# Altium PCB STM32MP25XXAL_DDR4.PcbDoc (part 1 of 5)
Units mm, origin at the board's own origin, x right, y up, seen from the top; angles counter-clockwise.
Board outline 125 x 95 mm, 6 copper layers (Top Layer, Signal Layer 1, Signal Layer 2, Signal Layer 3, Signal Layer 4, Bottom Layer), stack 1.403 mm thick; 220 components, 316 nets, 1103 pads, 939 vias.
Unrouted connection lines stored in the file: 5.
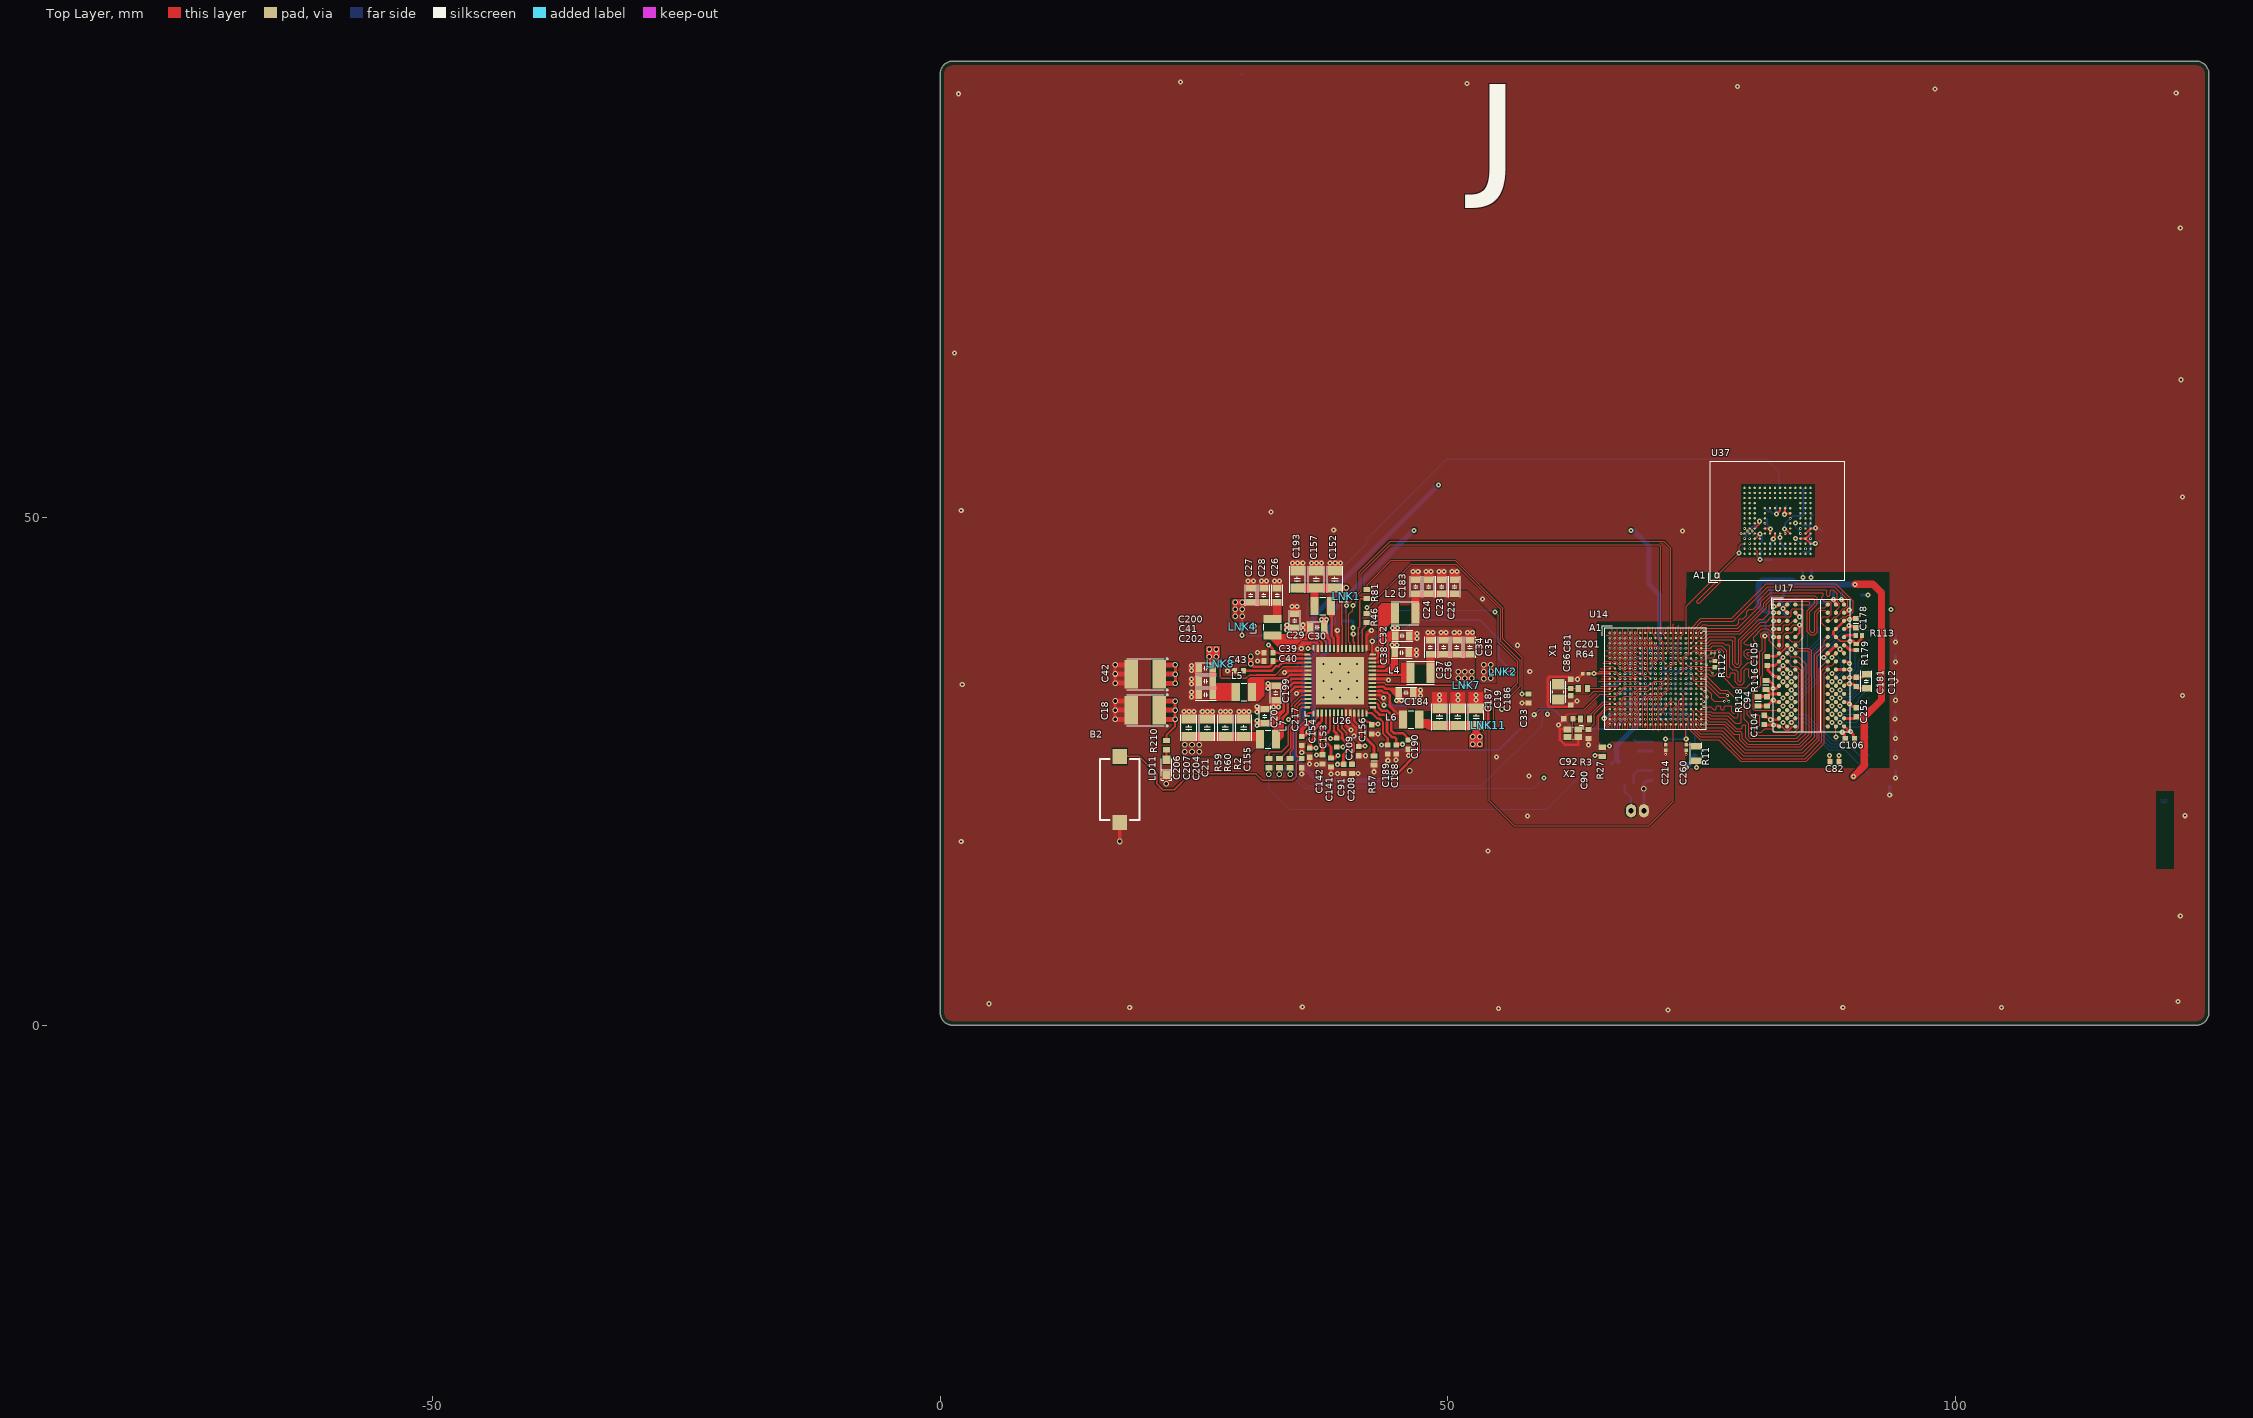
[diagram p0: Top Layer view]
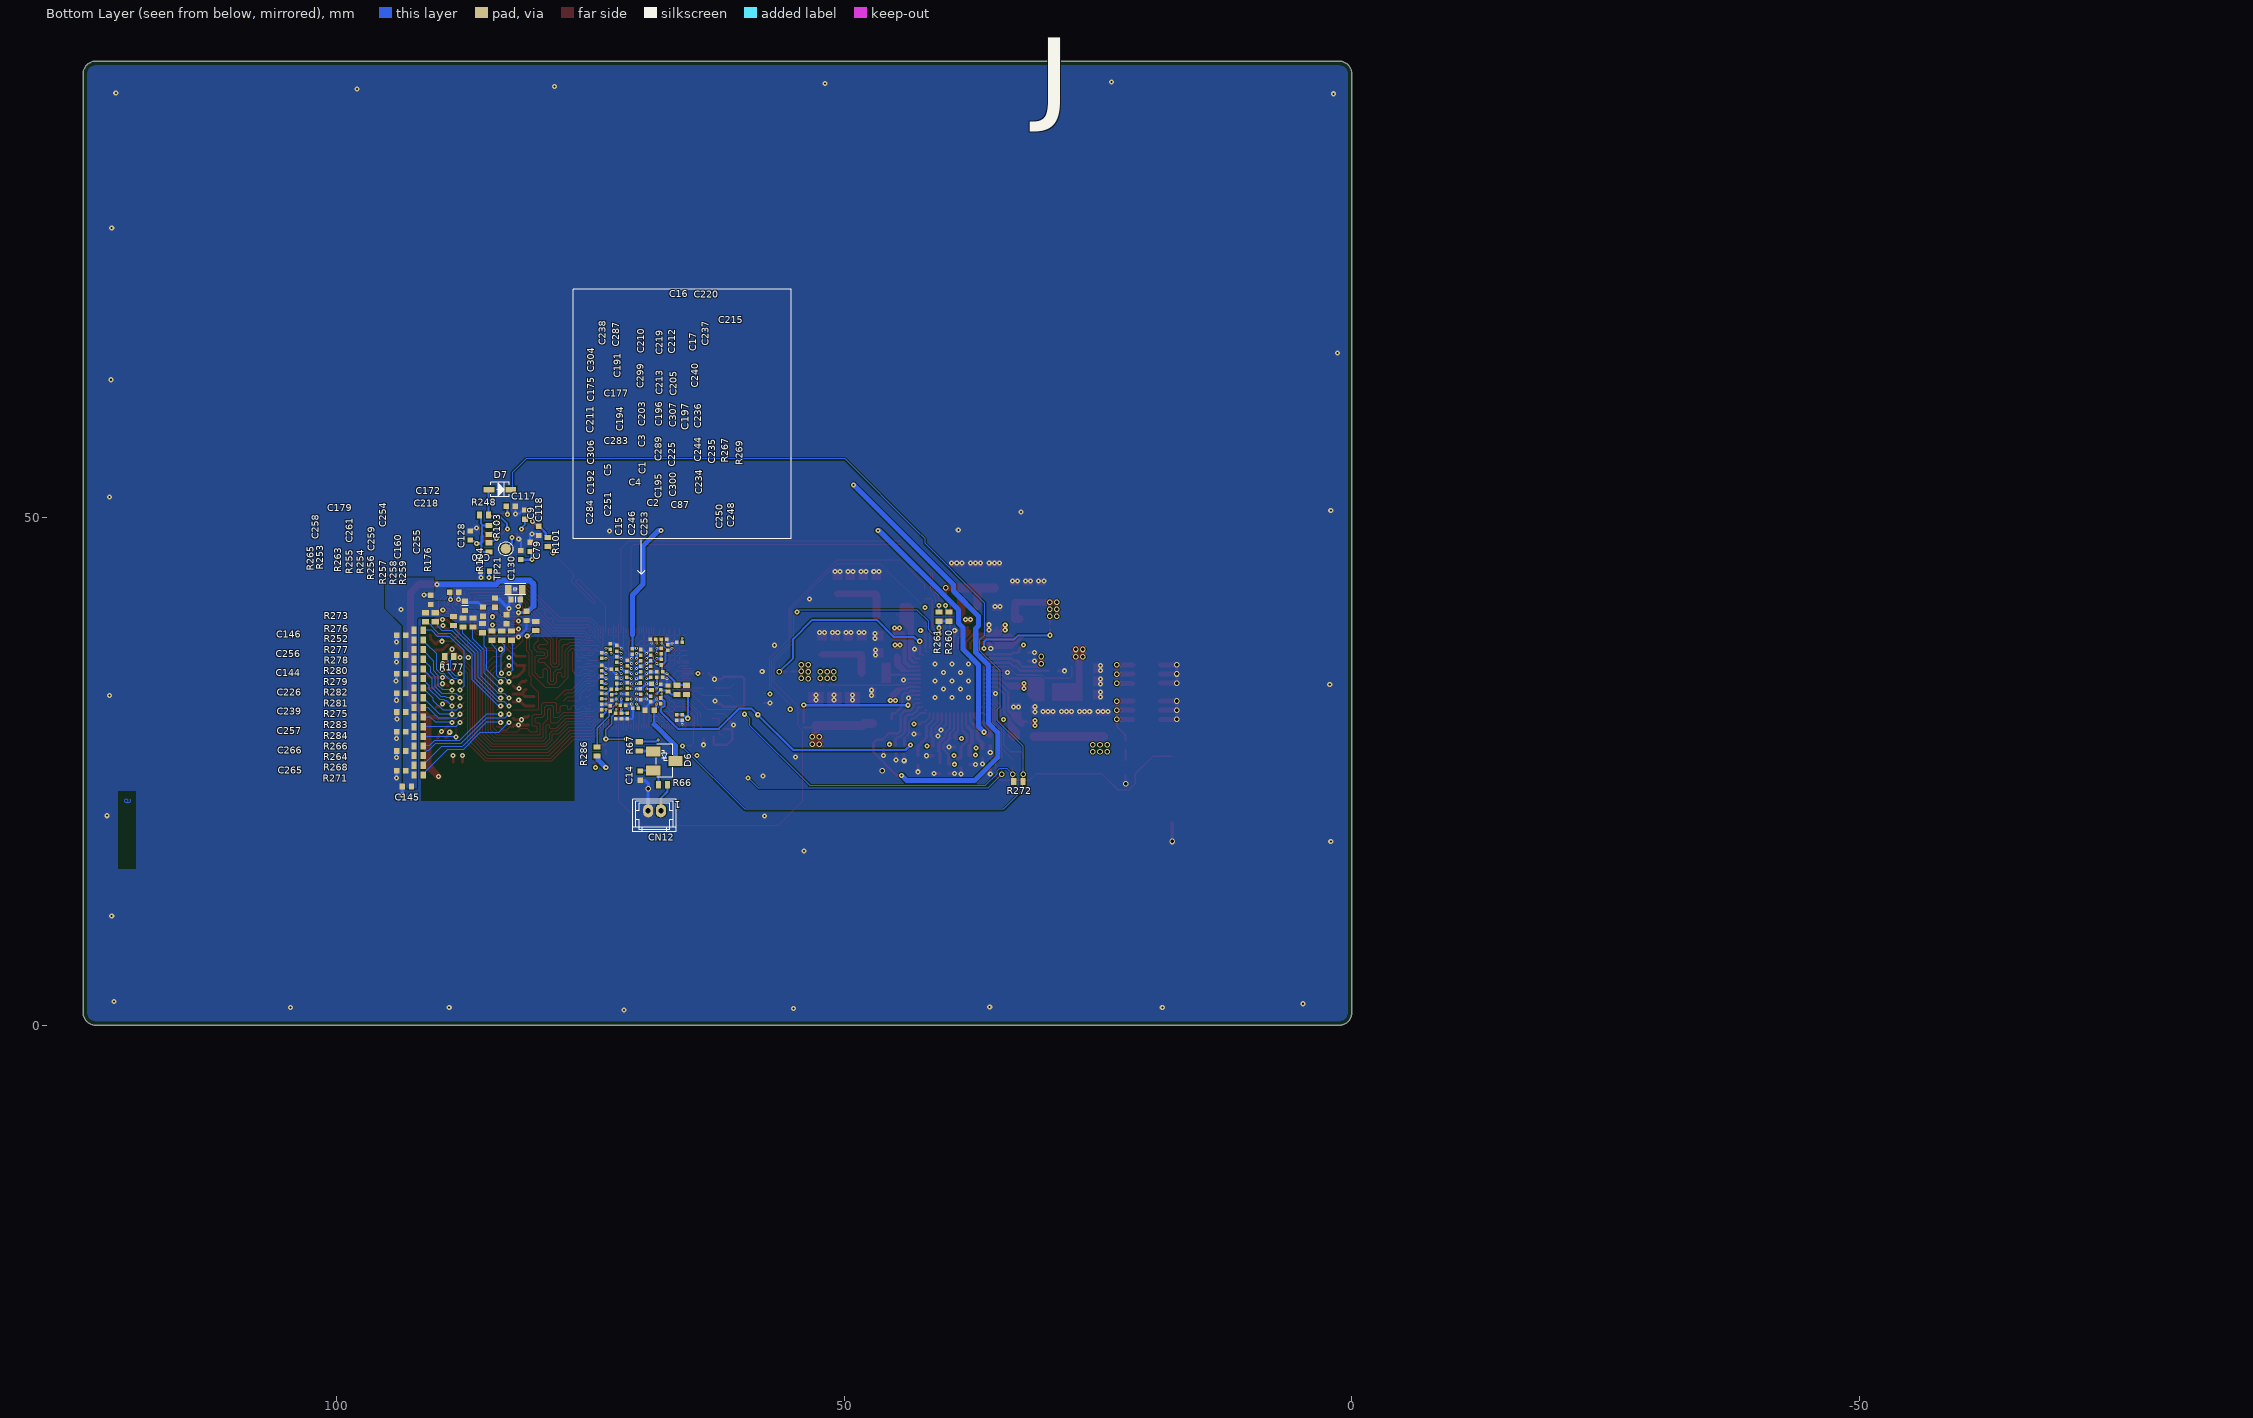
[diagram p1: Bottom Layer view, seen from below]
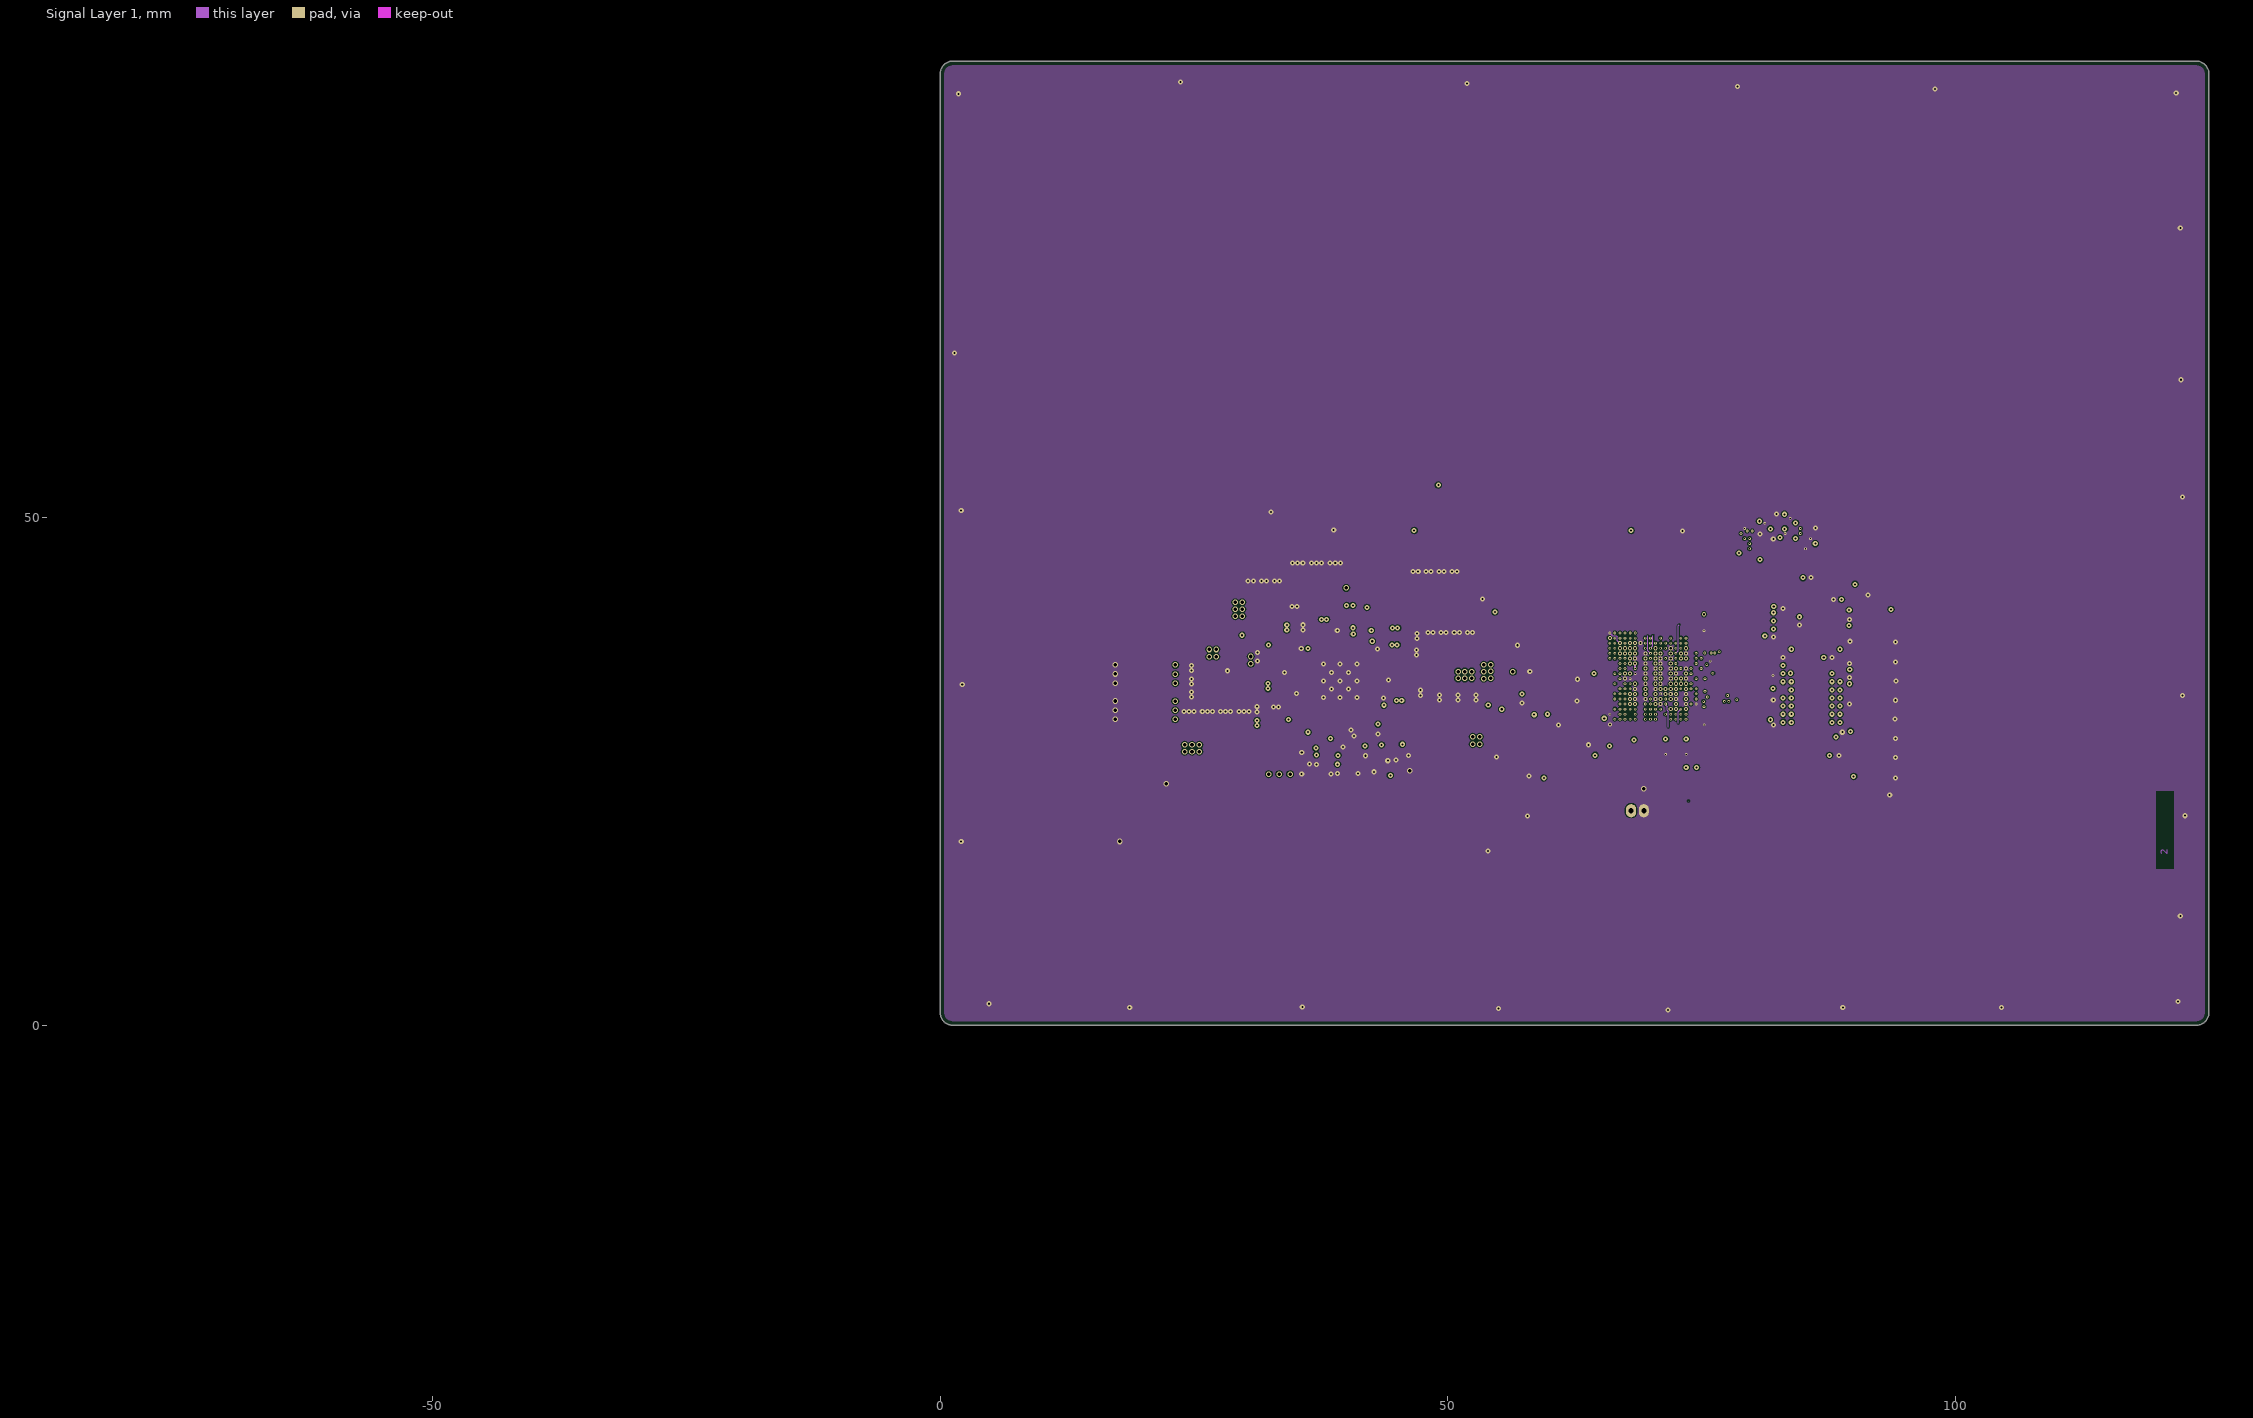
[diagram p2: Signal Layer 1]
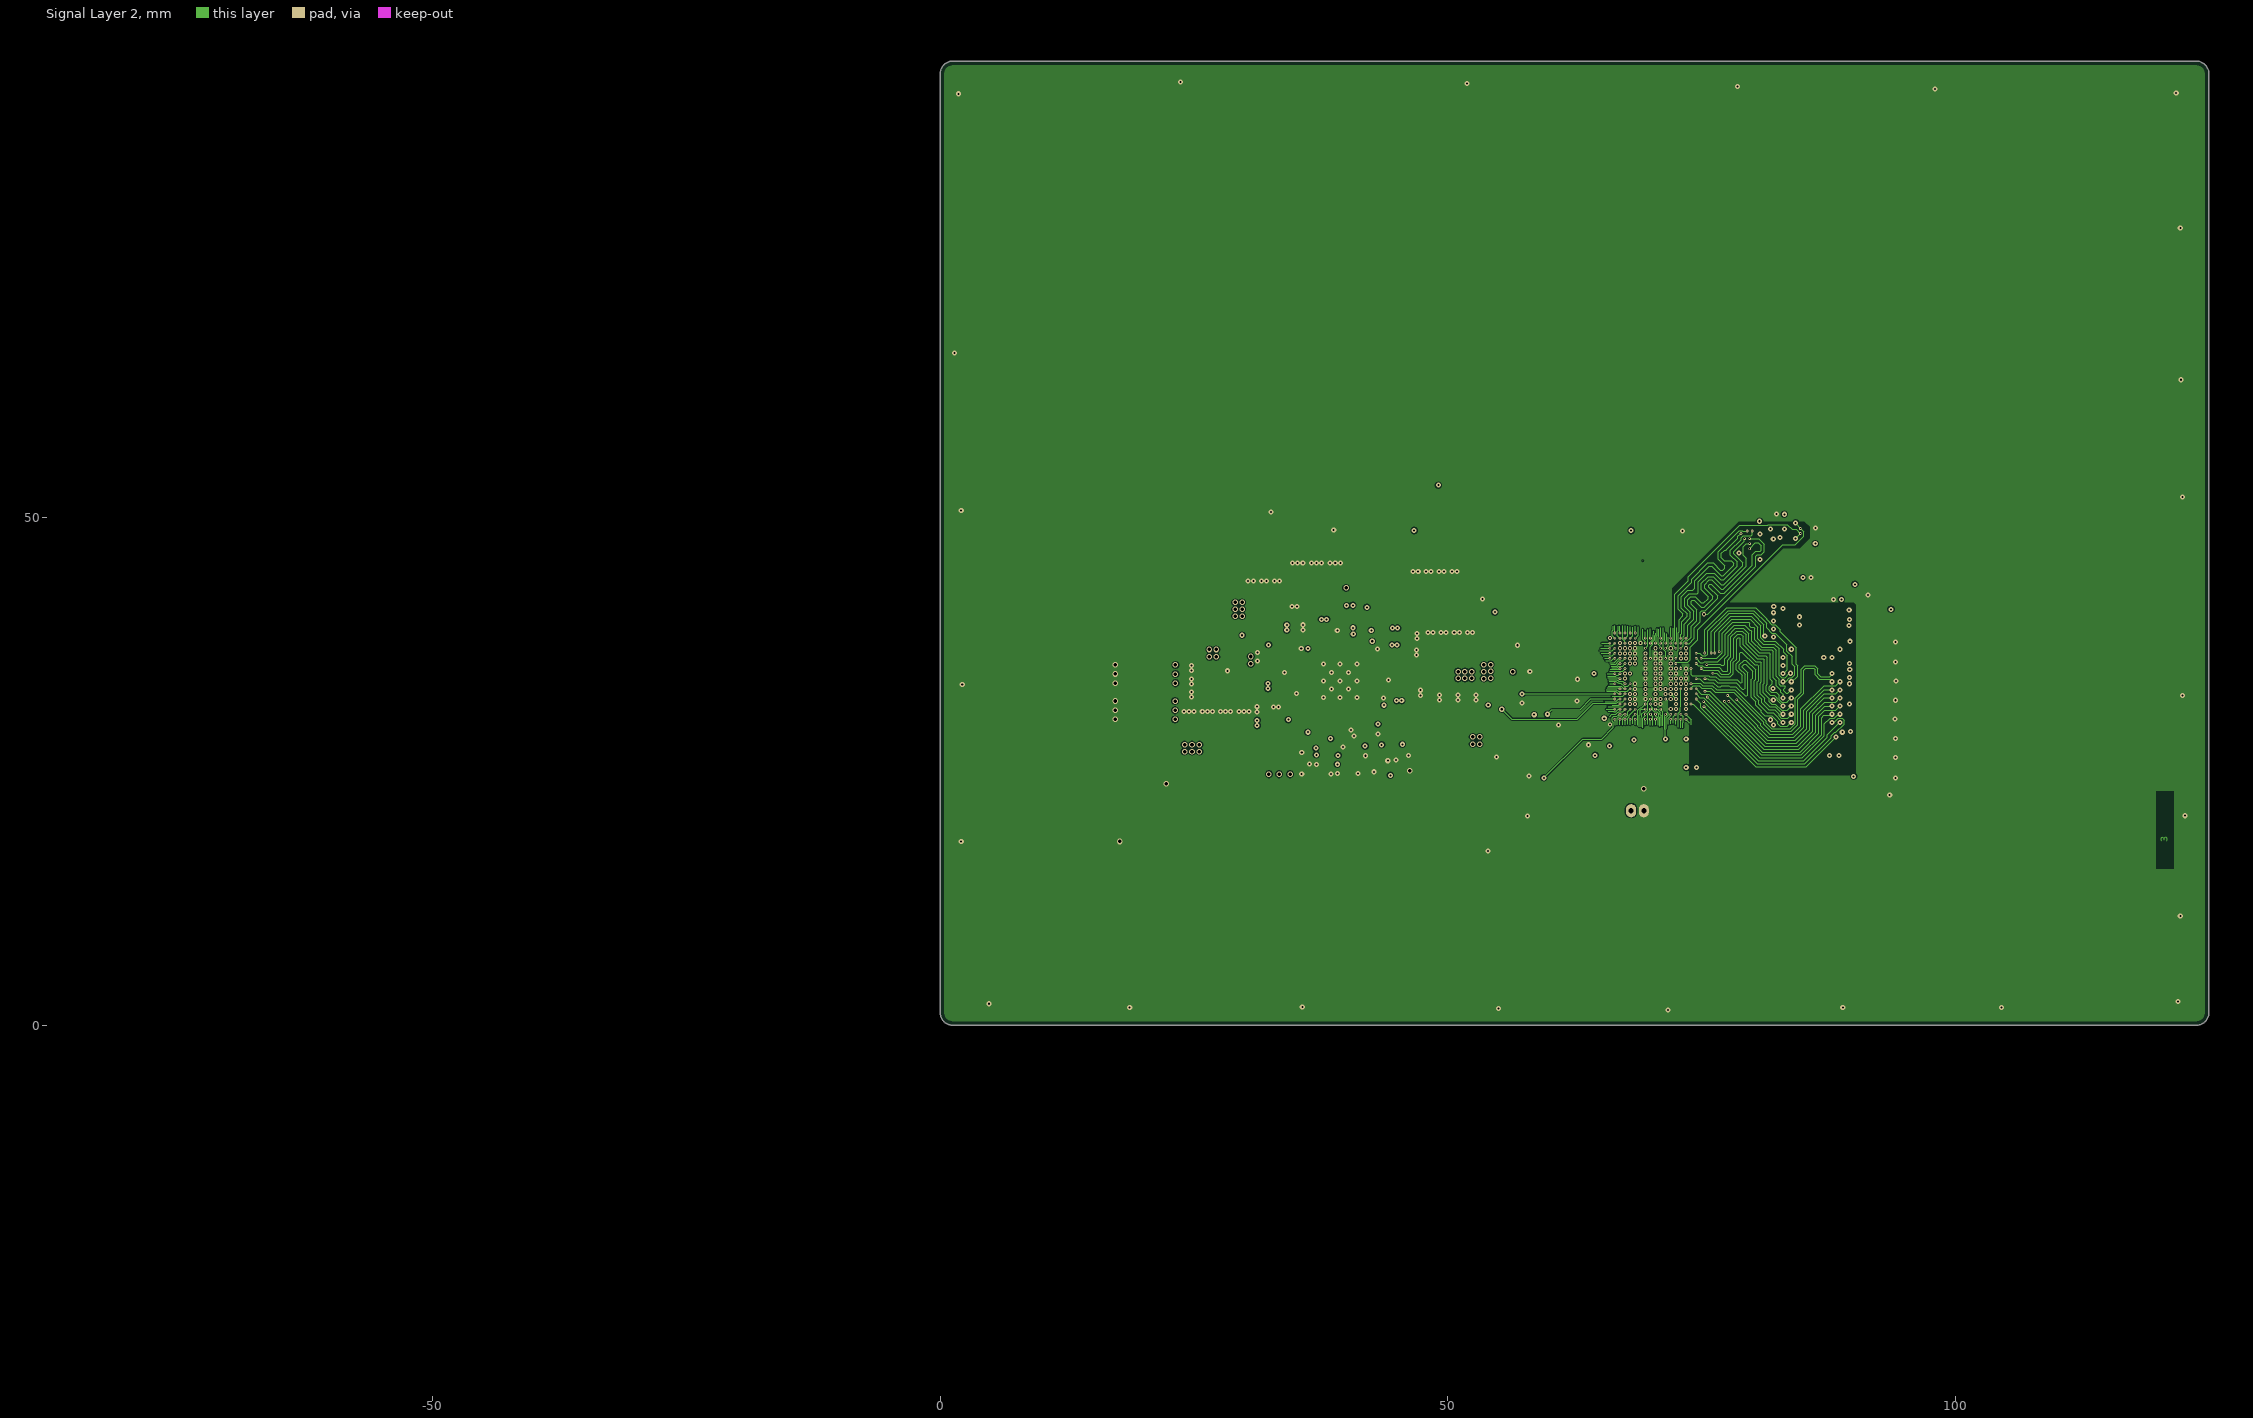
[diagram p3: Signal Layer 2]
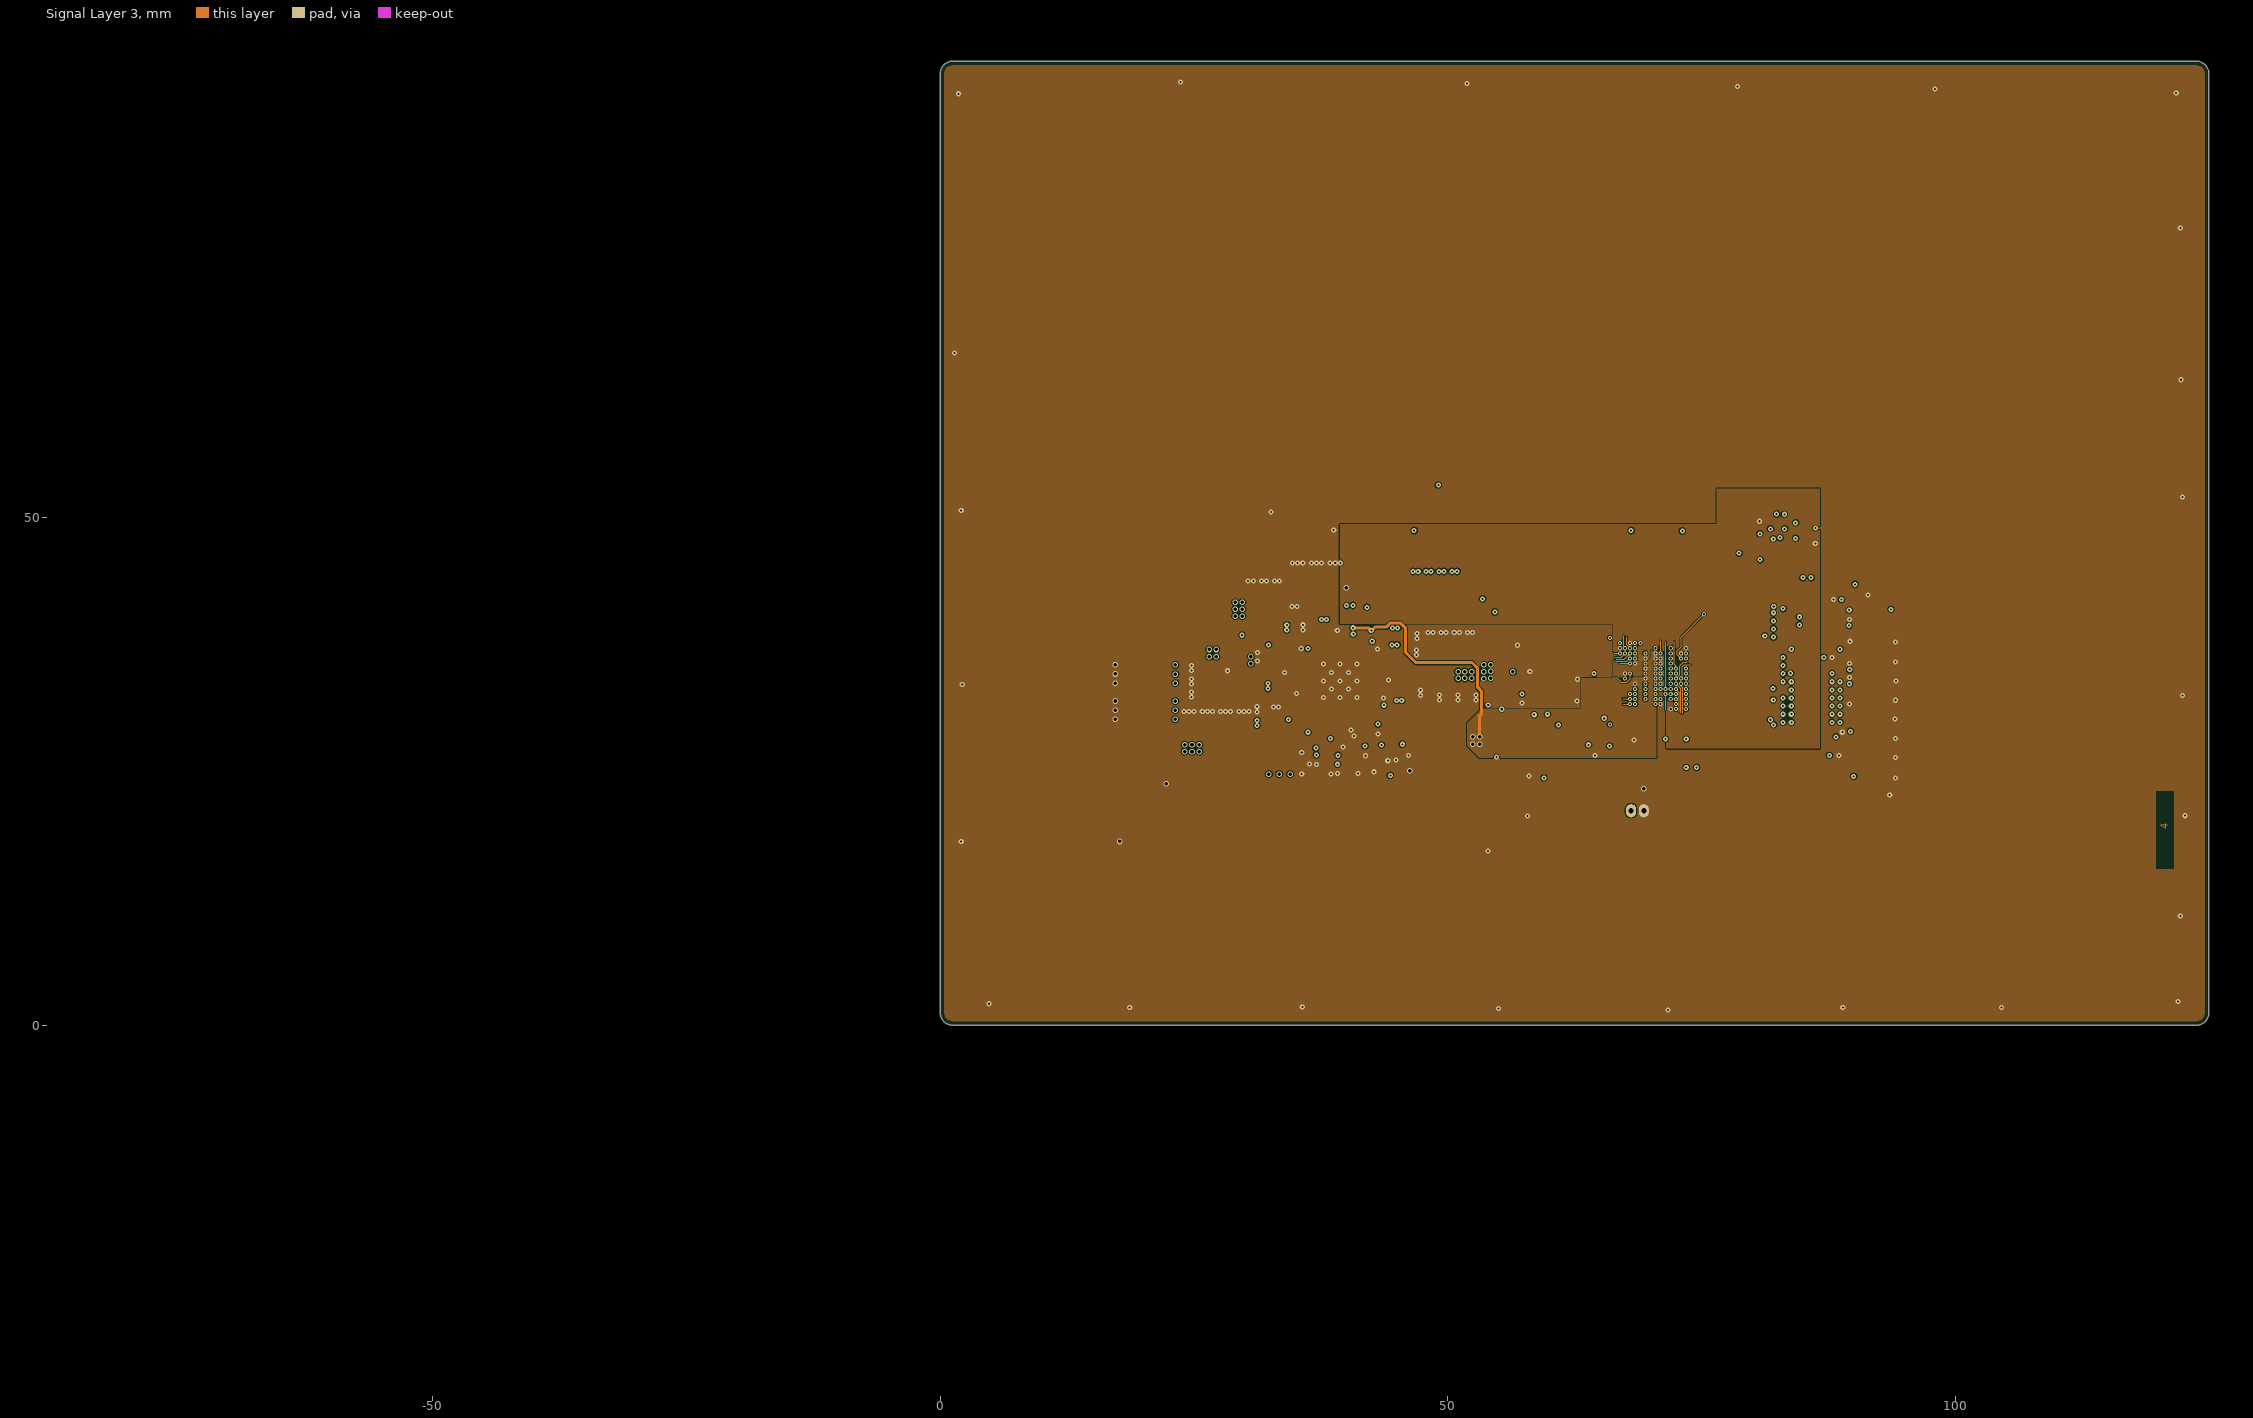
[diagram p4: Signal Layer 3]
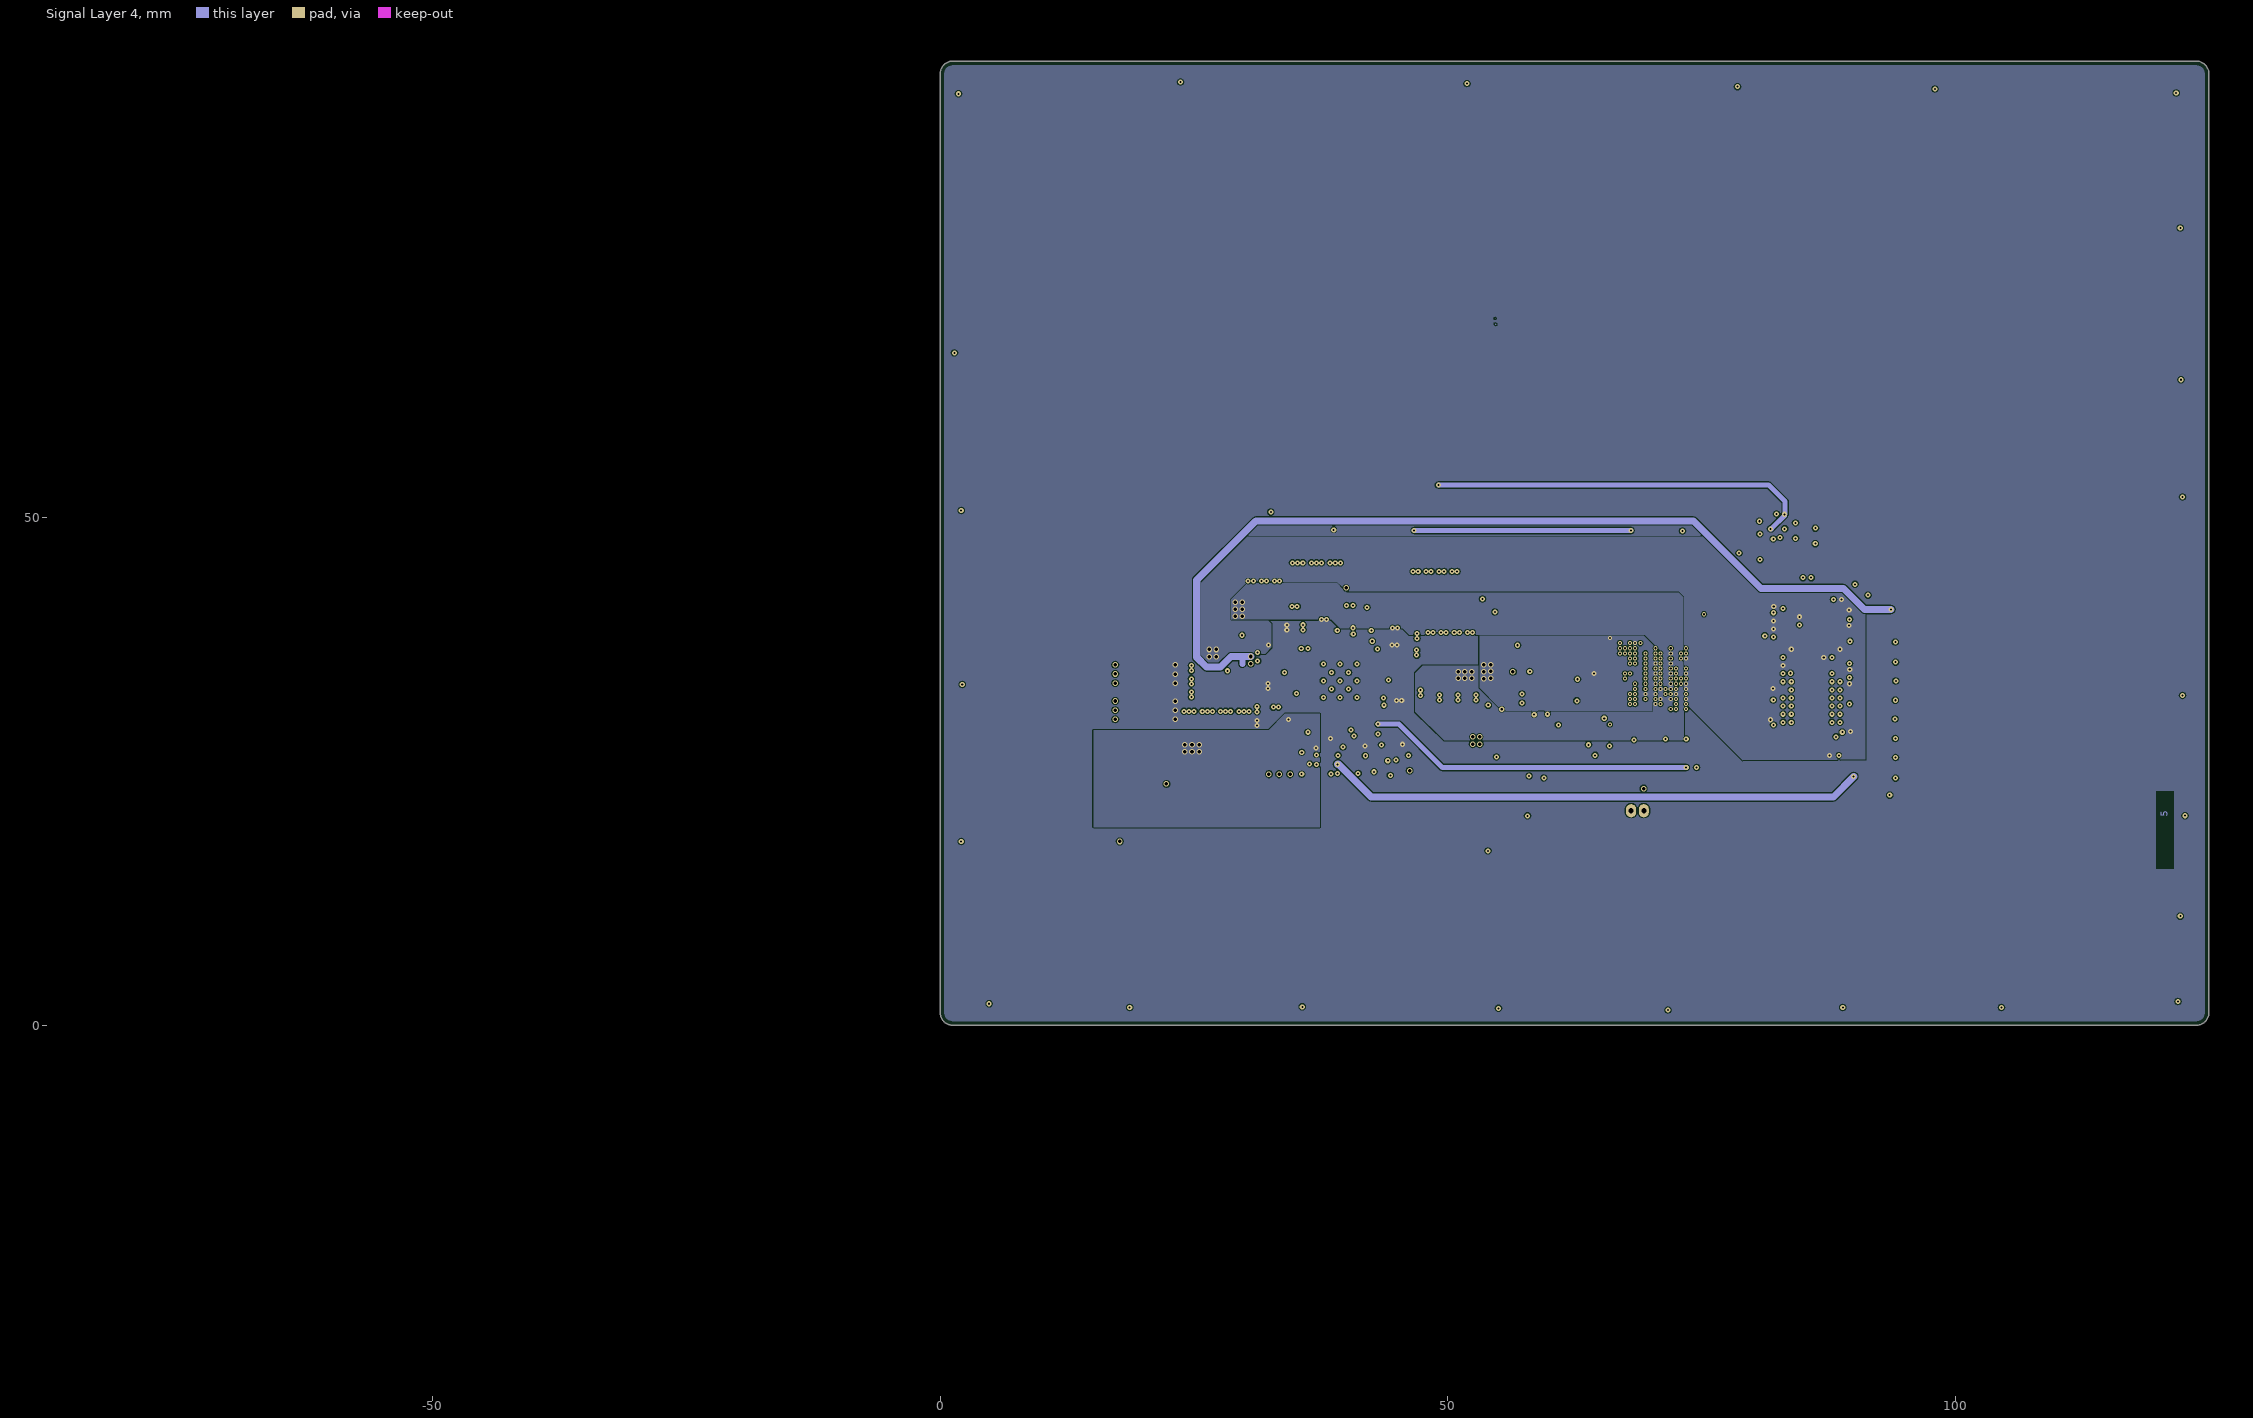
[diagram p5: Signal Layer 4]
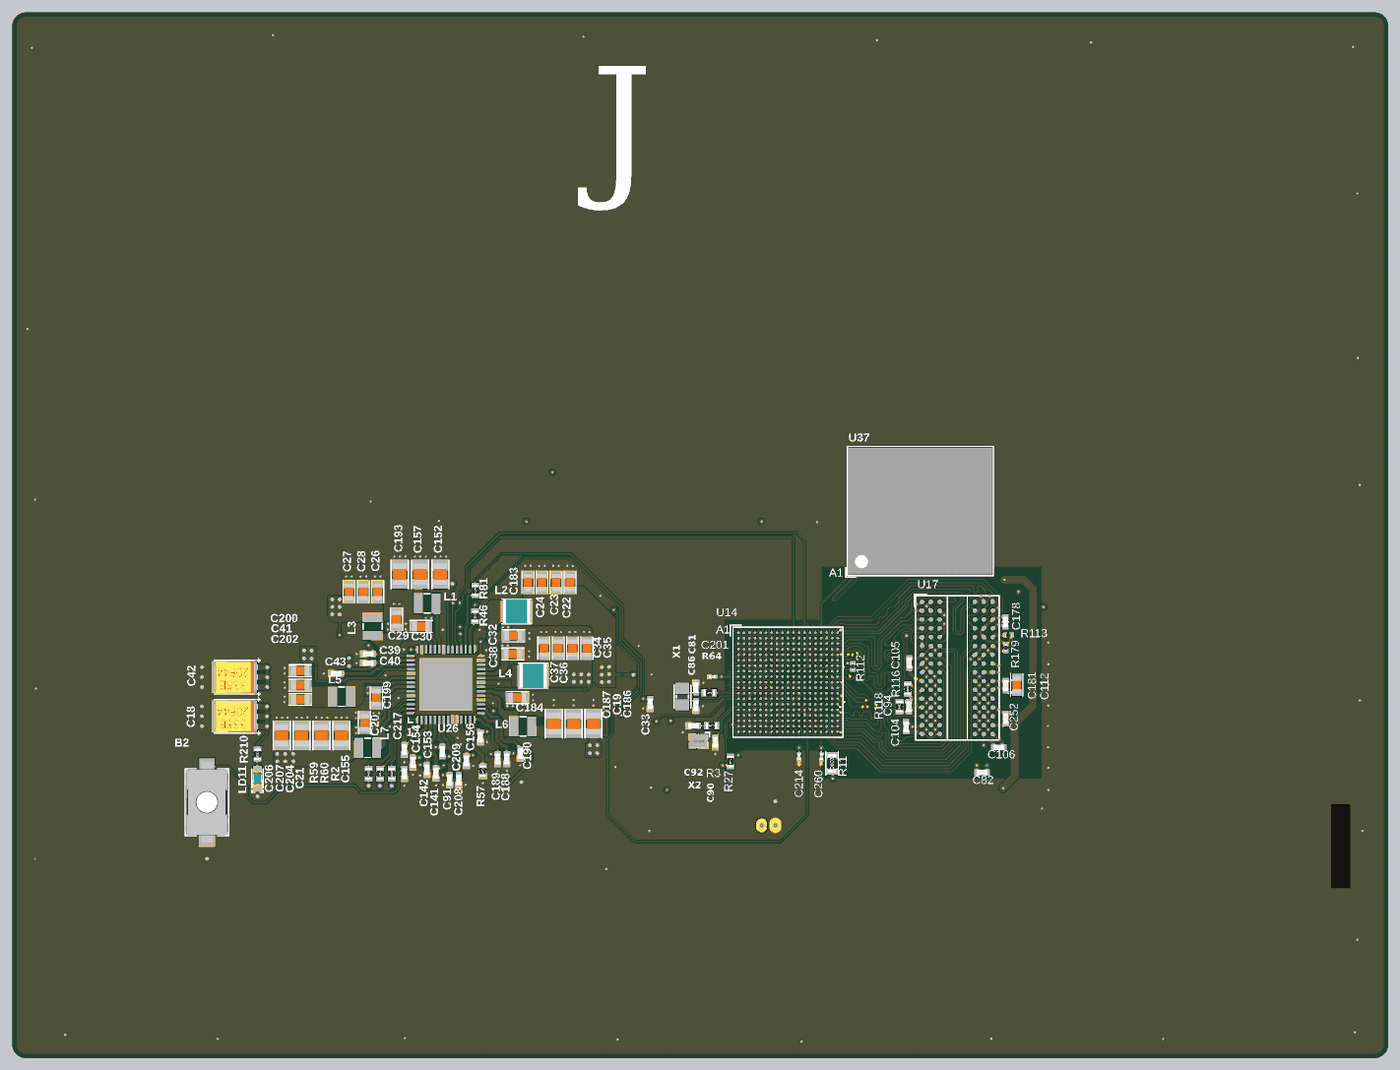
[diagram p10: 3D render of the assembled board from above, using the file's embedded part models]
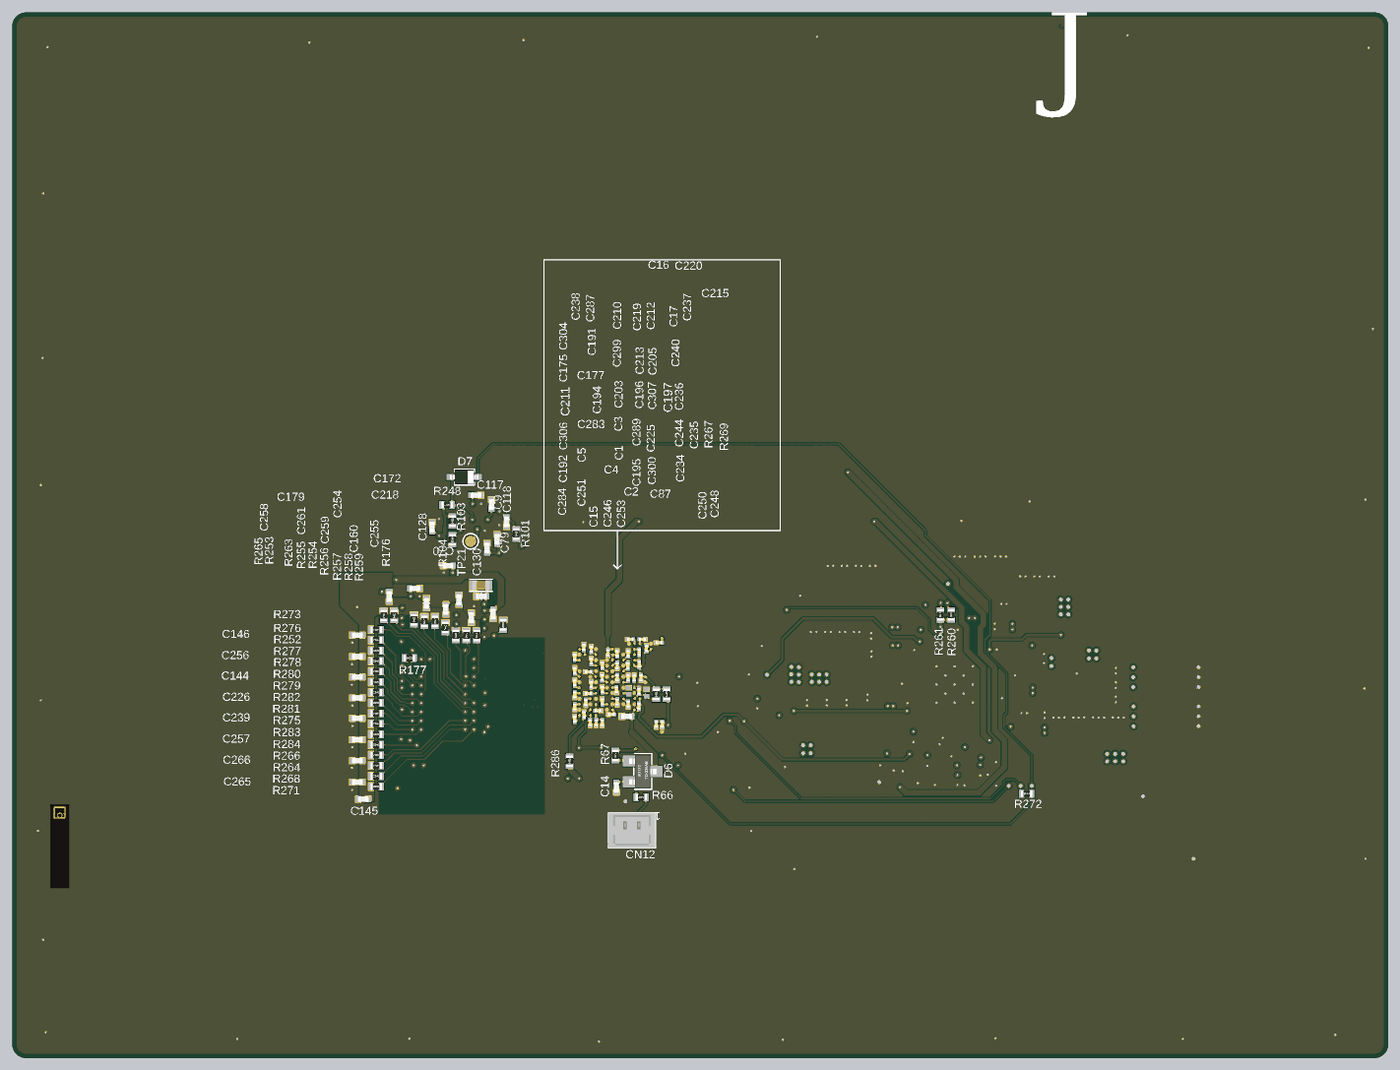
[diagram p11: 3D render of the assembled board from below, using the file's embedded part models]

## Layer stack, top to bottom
Top Solder: solder mask 0.025, Solder Resist, Dk 3.5
Top Layer: signal copper 0.046
Dielectric 1: prepreg 0.071, Dk 4.21
Signal Layer 1: signal copper 0.035
Dielectric 2: prepreg 0.094, Dk 4.09
Signal Layer 2: signal copper 0.023
Dielectric 3: core 0.865, Dk 4.68
Signal Layer 3: signal copper 0.023
Dielectric 4: prepreg 0.094, Dk 4.09
Signal Layer 4: signal copper 0.035
Dielectric5: prepreg 0.071, Dk 4.21
Bottom Layer: signal copper 0.046
Bottom Solder: solder mask 0.025, Solder Resist, Dk 3.5

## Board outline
0,1.27 ccw(c1.27,1.27) 1.27,0 123.73,0 ccw(c123.73,1.27) 125,1.27 125,93.73 ccw(c123.73,93.73) 123.73,95 1.27,95 ccw(c1.27,93.73) 0,93.73

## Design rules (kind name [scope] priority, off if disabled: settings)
BoardOutlineClearance [All] p1: gap=0.4 ignorepadtopadclearanceinfootprint=FALSE except(0: Arc-SplitContinuation Track-SplitContinuation SMDPad-SplitContinuation THPad-SplitContinuation Via-SplitContinuation Fill-SplitContinuation Poly-SplitContinuation Region-SplitContinuation Text-SplitContinuation)
Clearance [All] p1: gap=0.1 ignorepadtopadclearanceinfootprint=FALSE except(0: Arc-Hole SMDPad-Via SMDPad-Hole THPad-Hole Via-Via Via-Hole Fill-Hole Poly-Hole Region-Hole Text-Hole; 0.082: Track-Track Track-SMDPad Track-Via; 0.15: Arc-Fill Track-Fill SMDPad-Fill THPad-Fill Via-Fill Fill-Fill; 0.2: THPad-THPad)
ComponentClearance [HasFootprint('TP_SMD_1MM') vs HasFootprint('No Footprint')] p1: gap=0.2 collisioncheckmode=3 verticalgap=0.2 showdistances=FALSE
DiffPairsRouting [All] p1: maxlimit=0.16 minlimit=0.082 mostfreqgap=0.16 toplayer_mingap=0.16 toplayer_minwidth=0.075 toplayer_maxwidth=0.16 toplayer_prefwidth=0.09 midlayer1_minwidth=0.075 midlayer1_maxwidth=0.16 midlayer1_prefwidth=0.09 midlayer2_minwidth=0.075 midlayer2_maxwidth=0.16 midlayer2_prefwidth=0.09 midlayer3_minwidth=0.075 midlayer3_maxwidth=0.16 midlayer3_prefwidth=0.09 midlayer4_minwidth=0.075 midlayer4_maxwidth=0.16 midlayer4_prefwidth=0.09 bottomlayer_minwidth=0.075 bottomlayer_maxwidth=0.16 bottomlayer_prefwidth=0.09 maxuncoupledlength=12.7
FanoutControl Fanout_BGA [IsBGA] p1: bgadir=Out bgaviamode=Closest fanoutstyle=Auto fanoutdirection=Alternating viagrid=0.025 // Fanout_BGA (Default Rule)
FanoutControl Fanout_LCC [IsLCC] p2: bgadir=Out bgaviamode=Closest fanoutstyle=Auto fanoutdirection=Alternating viagrid=0.025 // Fanout_LCC (Default Rule)
FanoutControl Fanout_SOIC [IsSOIC] p3: bgadir=Out bgaviamode=Closest fanoutstyle=Auto fanoutdirection=Alternating viagrid=0.025 // Fanout_SOIC (Default Rule)
FanoutControl Fanout_Small [(CompPinCount < 5)] p4: bgadir=Out bgaviamode=Closest fanoutstyle=Auto fanoutdirection=OutThenIn viagrid=0.025 // Fanout_Small (Default Rule)
FanoutControl Fanout_Default [All] p5: bgadir=Out bgaviamode=Closest fanoutstyle=Auto fanoutdirection=Alternating viagrid=0.025 // Fanout_Default (Default Rule)
HoleSize [All] p1: absolutevalues=TRUE maxlimit=10 minlimit=0.1 maxpercent=80.000 minpercent=20.000
HoleToHoleClearance [InDrillLayerPair('Signal Layer 3 - Signal Layer 4') vs InDrillLayerPair('Signal Layer 3 - Signal Layer 4')] p1: gap=0.26 allowstackedmicrovias=TRUE
MinimumSolderMaskSliver [All] p1: minsoldermaskwidth=0.1
PlaneConnect [All] p1: planeconnectstyle=Direct reliefexpansion=0.508 reliefentries=4 reliefconductorwidth=0.21 reliefairgap=0.21
PolygonConnect PolygonConnect_NO_FT [IsNamedPolygon('GND')] p1: connectstyle=Direct reliefconductorwidth=0.254 reliefentries=4 polygonreliefangle="90 Angle" airgapwidth=0.254
PolygonConnect [All] p2: connectstyle=Direct reliefconductorwidth=0.2 reliefentries=4 polygonreliefangle="90 Angle" airgapwidth=0.2
RoutingVias [All] p1: holewidth=0.2 width=0.4 viastyle="Through Hole" minholewidth=0.1 minwidth=0.26 maxholewidth=0.35 maxwidth=0.6
ShortCircuit ShortCircuit_Link200 [InPadClass('PC_LINK200')] p1: allowed=TRUE
SilkToSilkClearance [All] p1: silktosilkclearance=0.2
SilkToSolderMaskClearance [IsPad] p1: minsilkscreentomaskgap=0.2 clearancetoexposedcopper=TRUE
SolderMaskExpansion [All] p1: expansion=0.05 istentingtop=FALSE
Width [All] p1: maxlimit=10 minlimit=0.075 preferedwidth=0.1 toplayer_prefwidth=0.09 midlayer2_prefwidth=0.09 minimp=50.000000 maximp=50.000000 favimp=50.000000
16 further rules are at their usual default settings.

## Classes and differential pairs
differential pair DDR_DQS1: +DDR_DQS1_P -DDR_DQS1_N
differential pair DDR_DQS0: +DDR_DQS0_P -DDR_DQS0_N
differential pair DDR_CLK: +DDR_CLK_P -DDR_CLK_N

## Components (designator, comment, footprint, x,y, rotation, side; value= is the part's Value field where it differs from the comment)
B2 "SW_PUSH_SMD_2P" SWI_WE_434121025816 17.693,23.243 r90 top value=434121025816
C1 "1uF" C0201_MURATA_GRM033_H0P3 71.4,32.38 r270 bottom
C2 "1uF" C0201_MURATA_GRM033_H0P3 70.575,31.225 r180 bottom
C3 "1uF" C0201_MURATA_GRM033_H0P3 71.4,33.48 r270 bottom
C4 "1uF" C0201_MURATA_GRM033_H0P3 71.795,31.555 r0 bottom
C5 "1uF" C0201_MURATA_GRM033_H0P3 72.9,32.3 r90 bottom
C9 "Capacitor" C0402 81.451,50.313 r270 bottom value=100nF
C14 "Capacitor" C0402 70.117,24.601 r90 bottom value=2.2uF
C15 "Capacitor" C0201_MURATA_GRM033_H0P3 72.5,30.47 r90 bottom value=1uF
C16 "Capacitor" C0201_MURATA_GRM033_H0P3 68.855,38.05 r180 bottom value=100nF
C17 "Capacitor" C0201_MURATA_GRM033_H0P3 68.045,36.875 r90 bottom value=100nF
C18 "Cap_POL_TANA" CPOL_TCJ-B_1210_H210 20.209,31.045 r180 top value=100uF
C19 "Capacitor" C0805 50.998,30.389 r270 top value=22uF
C20 "Capacitor" C0603 31.998,30.464 r270 top value=10uF
C21 "Capacitor" C0805 29.898,29.312 r270 top value=22uF
C22 "Capacitor" C0603 50.673,43.214 r270 top value=22uF
C23 "Capacitor" C0603 49.398,43.214 r270 top value=22uF
C24 "Capacitor" C0603 48.123,43.214 r270 top value=22uF
C26 "Capacitor" C0603 33.198,42.364 r270 top value=22uF
C27 "Capacitor" C0603 30.598,42.364 r270 top value=22uF
C28 "Capacitor" C0603 31.898,42.364 r270 top value=22uF
C29 "Capacitor" C0603 34.923,39.864 r270 top value=10uF
C30 "Capacitor" C0603 37.148,39.214 r0 top value=10uF
C32 "Capacitor" C0603 45.523,38.364 r180 top value=10uF
C33 "Capacitor" C0402 57.955,32.2 r90 top value=10nF
C34 "Capacitor" C0603 50.898,37.239 r270 top value=22uF
C35 "Capacitor" C0603 52.198,37.239 r270 top value=22uF
C36 "Capacitor" C0603 49.598,37.239 r270 top value=22uF
C37 "Capacitor" C0603 48.298,37.239 r270 top value=22uF
C38 "Capacitor" C0603 45.473,36.714 r180 top value=10uF
C39 "Capacitor" C0402 32.343,36.714 r0 top value=10uF
C40 "Capacitor" C0402 32.343,35.889 r0 top value=10uF
C41 "Capacitor" C0603 26.173,33.889 r0 top value=22uF
C42 "Cap_POL_TANA" CPOL_TCJ-B_1210_H210 20.209,34.607 r180 top value=100uF
C43 "Capacitor" C0402 29.433,34.939 r0 top value=1uF
C70 "Capacitor" C0402 85.4,44.745 r180 bottom value=100nF
C79 "Capacitor" C0402 80.946,47.138 r270 bottom value=2.2uF
C81 "Capacitor" C0402 62.112,33.645 r90 top value=6.8pF
C82 "Capacitor" C0402 88.1,25.95 r180 top value=100nF
C86 "Capacitor" C0402 62.112,32.02 r270 top value=6.8pF
C87 "" C0402 69.175,31.05 r180 bottom value=100nF
C90 "Capacitor" C0402 63.865,28.706 r90 top value=6.8pF
C91 "Capacitor" C0402 39.748,25.269 r270 top value=4.7uF
C92 "Capacitor" C0402 61.881,30.192 r180 top value=6.8pF
C94 "Capacitor" C0402 81.45,31.925 r90 top value=100nF
C104 "Capacitor" C0402 81.2,30.1 r90 top value=100nF
C105 "Capacitor" C0402 81.475,35.9 r90 top value=100nF
C106 "Capacitor" C0402 89.625,28.225 r0 top value=100nF
C112 "Capacitor" C0603 91.25,33.9 r270 top value=10uF
C117 "Capacitor" C0402 82.861,51.148 r0 bottom value=2.2uF
C118 "Capacitor" C0402 80.096,48.713 r90 bottom value=100nF
C128 "Capacitor" C0402 86.85,48.25 r270 bottom value=2.2uF
C130 "Capacitor" C0402 81.864,46.338 r270 bottom value=100nF
C141 "Capacitor" C0402 38.498,25.889 r270 top value=4.7uF
C142 "Capacitor" C0402 37.673,26.199 r270 top value=4.7uF
C144 "Capacitor" C0402 93.65,34.625 r180 bottom value=100nF
C145 "Capacitor" C0402 93.1,23.525 r180 bottom value=10uF
C146 "Capacitor" C0402 93.65,38.425 r180 bottom value=100nF
C152 "Capacitor" C0805 38.898,43.939 r270 top value=22uF
C153 "Capacitor" C0402 39.073,27.859 r90 top value=1uF
C154 "Capacitor" C0402 36.398,26.864 r90 top value=1uF
C155 "Capacitor" C0402 35.625,25.834 r90 top value=10nF
C156 "Capacitor" C0402 42.523,29.159 r90 top value=4.7uF
C157 "Capacitor" C0805 37.048,43.939 r270 top value=22uF
C160 "Capacitor" C0402 83.29,40.005 r270 bottom locked value=100nF
C172 "Capacitor" C0603 82.41,42.955 r180 bottom locked value=10uF
C175 "Capacitor" C0201_MURATA_GRM033_H0P3 73.9,35.2 r90 bottom value=1uF
C177 "Capacitor" C0201_MURATA_GRM033_H0P3 72.675,35.1 r0 bottom value=1uF
C178 "Capacitor" C0402 90.225,39.625 r270 top value=100nF
C179 "Capacitor" C0402 88.43,42.665 r0 bottom locked value=100nF
C181 "Capacitor" C0402 90.24,33.845 r270 top value=100nF
C183 "Capacitor" C0603 46.848,43.214 r270 top value=22uF
C184 "Capacitor" C0603 45.895,32.764 r180 top value=10uF
C186 "Capacitor" C0805 52.798,30.389 r270 top value=22uF
C187 "Capacitor" C0805 49.198,30.389 r270 top value=22uF
C188 "Capacitor" C0402 44.923,27.179 r90 top value=1uF
C189 "Capacitor" C0402 44.098,27.179 r90 top value=4.7uF
C190 "Capacitor" C0402 46.148,27.654 r270 top value=4.7uF
C191 "Capacitor" C0201_MURATA_GRM033_H0P3 72.4,36.05 r90 bottom value=1uF
C192 "Capacitor" C0201_MURATA_GRM033_H0P3 73.9,31.9 r270 bottom value=1uF
C193 "Capacitor" C0805 35.198,43.939 r270 top value=22uF
C194 "Capacitor" C0201_MURATA_GRM033_H0P3 72.4,33.95 r270 bottom value=1uF
C195 "Capacitor" C0201_MURATA_GRM033_H0P3 70.05,32.35 r270 bottom value=1uF
C196 "Capacitor" C0201_MURATA_GRM033_H0P3 70.05,34.55 r90 bottom value=1uF
C197 "Capacitor" C0201_MURATA_GRM033_H0P3 68.5,34.55 r270 bottom value=1uF
C199 "Capacitor" C0603 33.073,32.739 r90 top value=10uF
C200 "Capacitor" C0603 26.173,35.189 r0 top value=22uF
C201 "Capacitor" C0201_MURATA_GRM033_H0P3 63.6,34.65 r0 top value=100nF
C202 "Capacitor" C0603 26.173,32.589 r0 top value=22uF
C203 "Capacitor" C0201_MURATA_GRM033_H0P3 71.425,34.575 r90 bottom value=1uF
C204 "Capacitor" C0805 28.098,29.312 r270 top value=22uF
C205 "Capacitor" C0201_MURATA_GRM033_H0P3 69.075,35.65 r270 bottom value=1uF
C206 "Capacitor" C0805 24.498,29.312 r270 top value=22uF
C207 "Capacitor" C0805 26.298,29.312 r270 top value=22uF
C208 "Capacitor" C0402 40.573,25.269 r270 top value=4.7uF
C209 "Capacitor" C0402 41.248,27.009 r90 top value=4.7uF
C210 "Capacitor" C0201_MURATA_GRM033_H0P3 70.88,36.83 r90 bottom value=100nF
C211 "Capacitor" C0201_MURATA_GRM033_H0P3 73.9,34.1 r90 bottom value=1uF
C212 "Capacitor" C0201_MURATA_GRM033_H0P3 69.05,36.75 r270 bottom value=100nF
C213 "Capacitor" C0201_MURATA_GRM033_H0P3 70.05,35.65 r90 bottom value=1uF
C214 "Capacitor" C0201_MURATA_GRM033_H0P3 71.475,27.375 r90 top value=1uF
C215 "Capacitor" C0201_MURATA_GRM033_H0P3 66.25,37.745 r180 bottom value=100nF
C217 "Capacitor" C0402 35.623,28.009 r270 top value=4.7uF
C218 "Capacitor" C0402 82.375,41.95 r180 bottom value=100nF
C219 "Capacitor" C0201_MURATA_GRM033_H0P3 70.05,36.75 r270 bottom value=100nF
C220 "Capacitor" C0201_MURATA_GRM033_H0P3 67.755,38.05 r0 bottom value=100nF
C225 "Capacitor" C0201_H0P5 68.995,33.35 r270 bottom value=4.7uF
C226 "Capacitor" C0402 93.65,32.725 r180 bottom value=100nF
C234 "Capacitor" C0201_MURATA_GRM033_H0P3 68.07,31.97 r90 bottom value=100nF
C235 "Capacitor" C0201_H0P5 67.375,33.2 r270 bottom value=2.2uF
C236 "Capacitor" C0201_MURATA_GRM033_H0P3 67.88,34.55 r90 bottom value=100nF
C237 "Capacitor" C0201_MURATA_GRM033_H0P3 67.38,37.225 r270 bottom value=100nF
C238 "Capacitor" C0201_MURATA_GRM033_H0P3 73.07,37.33 r270 bottom value=100nF
C239 "Capacitor" C0402 93.65,30.875 r180 bottom value=100nF
C240 "Capacitor" C0201_MURATA_GRM033_H0P3 68.045,35.775 r270 bottom value=100nF
C244 "Capacitor" C0201_MURATA_GRM033_H0P3 68.07,33.33 r270 bottom value=100nF
C246 "Capacitor" C0201_MURATA_GRM033_H0P3 71.95,30.47 r90 bottom value=100nF
C248 "Capacitor" C0201_MURATA_GRM033_H0P3 65.95,30.325 r90 bottom value=100nF
C250 "Capacitor" C0201_MURATA_GRM033_H0P3 66.5,30.325 r90 bottom value=1uF
C251 "Capacitor" C0201_MURATA_GRM033_H0P3 73.05,31.2 r270 bottom value=100nF
C252 "Capacitor" C0402 90.24,30.845 r270 top value=100nF
C253 "Capacitor" C0201_MURATA_GRM033_H0P3 71.4,30.47 r90 bottom value=100nF
C254 "Capacitor" C0402 84.42,41.645 r270 bottom locked value=10uF
C255 "Capacitor" C0402 81.31,40.345 r90 bottom value=100nF
C256 "Capacitor" C0402 93.65,36.475 r180 bottom value=100nF
C257 "Capacitor" C0402 93.65,28.925 r180 bottom value=100nF
C258 "Capacitor" C0402 90.75,41.925 r270 bottom locked value=100nF
C259 "Capacitor" C0402 85.6,40.755 r270 bottom locked value=100nF
C260 "Capacitor" C0201_MURATA_GRM033_H0P3 73.525,27.375 r90 top value=1uF
C261 "Capacitor" C0402 87.37,41.325 r270 bottom locked value=100nF
C265 "Capacitor" C0402 93.65,25.075 r180 bottom value=100nF
C266 "Capacitor" C0402 93.65,27.025 r180 bottom value=100nF
C283 "Capacitor" C0201_MURATA_GRM033_H0P3 72.675,33.125 r180 bottom value=1uF
C284 "Capacitor" C0201_MURATA_GRM033_H0P3 73.9,30.8 r90 bottom value=1uF
C287 "Capacitor" C0201_MURATA_GRM033_H0P3 72.4,37.15 r270 bottom value=1uF
C289 "Capacitor" C0201_MURATA_GRM033_H0P3 70.1,33.45 r90 bottom value=1uF
C299 "Capacitor" C0201_MURATA_GRM033_H0P3 71.4,35.68 r270 bottom value=1uF
C300 "Capacitor" C0201_MURATA_GRM033_H0P3 69.05,32.15 r90 bottom value=1uF
C304 "Capacitor" C0201_MURATA_GRM033_H0P3 73.9,36.425 r90 bottom value=1uF
C306 "Capacitor" C0201_MURATA_GRM033_H0P3 73.9,33 r270 bottom value=1uF
C307 "Capacitor" C0201_MURATA_GRM033_H0P3 69.05,34.55 r90 bottom value=1uF
CN12 "" CON_MOLEX_53047-0210 68.699,21.141 r0 bottom value="Header 2x1"
D6 "DIODE_3P_DUAL_COMMON_CATHODE" DIO_SOT23 67.726,26.042 r270 bottom value=BAT54CFILM
D7 "BAT60JFILM" DIO_SOD323 83.93,52.788 r180 bottom
L1 "Inductor" IND_2016_MURATA_LQM2MPN2R2NG0 37.693,41.314 r180 top value=2.2uH
L2 "Inductor" IND_2520_TOKO_DFE252012P 45.813,40.589 r0 top value=0.68µH
L3 "Inductor" IND_2016_MURATA_LQM2MPN2R2NG0 32.748,39.214 r90 top value=0.68uH
L4 "Inductor" IND_2520_TOKO_DFE252012P 47.323,34.739 r0 top value=0.68µH
L5 "Inductor" IND_2016_MURATA_LQM2MPN2R2NG0 29.923,32.839 r180 top value=0.68uH
L6 "Inductor" IND_2016_MURATA_LQM2MPN2R2NG0 46.398,30.139 r0 top value=2.2uH
L7 "Inductor" IND_2016_MURATA_LQM2MPN2R2NG0 32.298,28.189 r180 top value=0.68uH
LD11 "LED_green" LED_0603_OSRAM_LG-Q396-PS-35_GREEN_1A2K_H0P4 22.284,25.411 r270 top value=GREEN
LNK1 "link_200" LINK200 39.998,42.262 r0 top
LNK2 "link_200" LINK200 55.439,34.839 r90 top
LNK4 "link_200" LINK200 29.748,39.264 r180 top
LNK7 "link_200" LINK200 51.848,33.489 r270 top
LNK8 "link_200" LINK200 27.598,35.637 r0 top
LNK11 "link_200" LINK200 53.998,29.579 r180 top
R2 "" R0402 34.478,25.834 r90 top value=0R
R3 "" R0402 63.531,30.192 r0 top value=0R
R11 "Resistor" R0603 74.475,26.775 r90 top value=0R
R27 "Resistor" R0402 65.225,26.95 r270 top value=10K
R46 "" R0402 42.048,40.137 r270 top value=0R
R57 "" R0402 42.748,26.089 r90 top value=0R
R59 "" R0402 32.378,25.834 r90 top value=0R
R60 "" R0402 33.428,25.834 r90 top value=0R
R64 "" R0402 63.312,33.195 r180 top value=0R
R66 "Resistor" R0402 67.866,23.699 r0 bottom value=20R
R67 "Resistor" R0402 70.199,27.491 r90 bottom value=0R
R81 "" R0402 42.061,42.487 r270 top value=0R
R101 "Resistor" R0402 79.211,47.608 r90 bottom value=10K
R103 "Resistor" R0402 85.007,48.794 r90 bottom value=10K
R104 "Resistor" R0402 85.011,47.088 r270 bottom value=10K
R112 "Resistor" R0201_H0P23 76.35,35.575 r270 top value=240R
R113 "Resistor" R0201_H0P23 90.5,38.425 r180 top value=240R
R116 "Resistor" R0402 81.35,33.535 r270 top value=1K
R118 "Resistor" R0402 80.58,31.925 r90 top value=1K
R176 "Resistor" R0402 80.4,39.35 r270 bottom value=10K
R177 "Resistor" R0402 88.92,36.35 r180 bottom locked value=100R
R179 "Resistor" R0201_H0P23 90.25,37.275 r270 top value=240R
R210 "Resistor" R0402 22.284,27.604 r270 top value=270R
R248 "Resistor" R0402 85.493,50.263 r0 bottom value=10K
R252 "Resistor" R0402 91.935,37.02 r0 bottom value=56R
R253 "Resistor" R0402 90.3,40.205 r90 bottom value=56R
R254 "Resistor" R0402 86.6,39.685 r90 bottom locked value=56R
R255 "Resistor" R0402 87.55,39.685 r90 bottom locked value=56R
R256 "Resistor" R0402 85.65,39.125 r90 bottom locked value=56R
R257 "Resistor" R0402 84.7,38.395 r90 bottom locked value=56R
R258 "Resistor" R0402 83.75,38.395 r90 bottom locked value=56R
R259 "Resistor" R0402 82.8,38.395 r90 bottom locked value=56R
R260 "Resistor" R0402 39.704,40.267 r270 bottom value=1K5
R261 "Resistor" R0402 40.679,40.267 r270 bottom value=1K5
R263 "Resistor" R0402 88.5,39.825 r90 bottom locked value=56R
R264 "Resistor" R0402 91.935,26.575 r0 bottom value=56R
R265 "Resistor" R0402 91.25,40.205 r90 bottom value=56R
R266 "Resistor" R0402 91.935,27.52 r0 bottom value=56R
R267 "" R0402 66.5,33.05 r90 bottom value=0R
R268 "Resistor" R0402 91.935,25.62 r0 bottom value=56R
R269 "" R0402 65.55,33.05 r270 bottom value=0R
R271 "Resistor" R0402 91.935,24.67 r0 bottom value=56R
R272 "Resistor" R0402 32.849,24.016 r0 bottom value=10K
R273 "Resistor" R0402 91.935,38.92 r0 bottom value=56R
R275 "Resistor" R0402 91.935,30.37 r0 bottom value=56R
R276 "Resistor" R0402 91.935,37.97 r0 bottom value=56R
R277 "Resistor" R0402 91.935,36.07 r0 bottom value=56R
R278 "Resistor" R0402 91.935,35.12 r0 bottom value=56R
R279 "Resistor" R0402 91.935,33.22 r0 bottom value=56R
R280 "Resistor" R0402 91.935,34.17 r0 bottom value=56R
R281 "Resistor" R0402 91.935,31.32 r0 bottom value=56R
R282 "Resistor" R0402 91.935,32.27 r0 bottom value=56R
R283 "Resistor" R0402 91.935,29.42 r0 bottom value=56R
R284 "Resistor" R0402 91.935,28.47 r0 bottom value=56R
R286 "" R0402 74.375,26.975 r90 bottom value=0R
TP21 "Test Point" TP_SMD_1MM 83.352,46.948 r90 bottom
U14 "STM32MP257FAL3" ICC_VFBGA361_10X10_P050 70.475,34.15 r0 top
U17 "MT40A2G16TBB-062E:F" ICC_FBGA96_TBB_7P5X13_P080 85.85,35.45 r0 top locked
U26 "STPMIC25APQR" ICC_QFN56-EPAD_6P5X6P5_P040 39.398,33.939 r90 top
U37 "eMMC_THGBMTG5D1LBAIL" ICC_P-WFBGA153_13X11P5_P050 82.5,49.7 r0 top value=THGBMTG5D1LBAIL
X1 "XTAL_2_PINS" CRY_NX2012SA_2P 60.886,32.845 r270 top value=32.768KHz
X2 "XTAL_4_PINS" CRY_NX1612SA_4P 62.331,28.781 r180 top value=40MHz

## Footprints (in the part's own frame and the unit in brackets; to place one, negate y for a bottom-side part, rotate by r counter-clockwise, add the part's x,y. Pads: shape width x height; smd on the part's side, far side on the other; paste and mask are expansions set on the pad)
C0201_H0P5 [mm] "MCD-01534"
  rect 0.4x0.5 smd mask+0.05: 1(-0.3,0) 2(0.3,0)
  body extent -0.35,-0.2 0.35,0.2, height 0.55
C0201_MURATA_GRM033_H0P3 [mm] "GRM033R60J105ME11"
  rect 0.35x0.35 smd mask+0.05: 1(-0.275,0) 2(0.275,0)
  body extent -0.32,-0.17 0.32,0.17, height 0.33
C0402 [mm]
  rect 0.51x0.56 smd mask+0.05: 1(-0.45,0) 2(0.45,0)
  body extent -0.5,-0.3 0.5,0.3, height 0.4
C0603 [mm]
  rect 0.64x0.89 smd mask+0.05: 1(-0.7,0) 2(0.7,0)
  silkscreen extent -1.05,-0.55 1.02,0.55, body extent -0.9,-0.5 0.9,0.5, height 1.4
C0805 [mm]
  rect 0.9x1.4 smd mask+0.05: 1(-0.85,0) 2(0.85,0)
  silkscreen extent -1.3,-0.77 1.3,0.77, body extent -1.1,-0.7 1.1,0.7, height 1.35
CON_MOLEX_53047-0210 [mm]
  oval 1x1.3 hole 0.5 mask+0.05: 1(-0.625,0) 2(0.625,0)
  silkscreen extent -2.12,-1.15 2.13,2.05, body extent -2.12,-1.15 2.13,2.05, height 4.2
CPOL_TCJ-B_1210_H210 [mm] "MCD-01791"
  rect 1.35x2.8 smd mask+0.05: 1(-1.375,0) 2(1.375,0)
  silkscreen extent -2.33,-1.68 1.85,1.68, body extent -1.85,-1.5 1.85,1.5, height 2.11
CRY_NX1612SA_4P [mm] "MCD-02262"
  rect 0.75x0.6 smd mask+0.038: 1(-0.525,-0.375) 2(0.525,-0.375) 3(0.525,0.375) 4(-0.525,0.375)
  silkscreen extent -1.02,-0.8 0.03,0.6, body extent -0.8,-0.6 0.8,0.6, height 0.51
CRY_NX2012SA_2P [mm]
  rect 1x1.25 smd mask+0.05: 1(-0.75,0) 2(0.75,0)
  silkscreen extent -1.05,-0.75 1.05,0.75, body extent -1.05,-0.63 1.05,0.63, height 0.6
DIO_SOD323 [mm]
  rect 1.06x0.54 smd mask+0.05: 1(-1.07,0) 2(1.07,0)
  silkscreen extent -0.9,-0.72 0.9,0.72, body extent -1.3,-0.78 1.3,0.78, height 1.17
DIO_SOT23 [mm]
  rect 1x1.4 smd mask+0.05: 1(-0.95,-1.1) 2(0.95,-1.1) 3(0,1.1)
  silkscreen extent -1.63,-0.82 1.63,0.82, body extent -1.56,-1.25 1.56,1.25, height 1.1
ICC_FBGA96_TBB_7P5X13_P080 [mm] "MCD-04020"
  round 0.42 smd mask+0.05: A1(-3.2,6) A2(-2.4,6) A3(-1.6,6) A7(1.6,6) A8(2.4,6) A9(3.2,6) B1(-3.2,5.2) B2(-2.4,5.2) B3(-1.6,5.2) B7(1.6,5.2) B8(2.4,5.2) B9(3.2,5.2) C1(-3.2,4.4) C2(-2.4,4.4) C3(-1.6,4.4) C7(1.6,4.4) C8(2.4,4.4) C9(3.2,4.4) D1(-3.2,3.6) D2(-2.4,3.6) D3(-1.6,3.6) D7(1.6,3.6) D8(2.4,3.6) D9(3.2,3.6) E1(-3.2,2.8) E2(-2.4,2.8) E3(-1.6,2.8) E7(1.6,2.8) E8(2.4,2.8) E9(3.2,2.8) F1(-3.2,2) F2(-2.4,2) F3(-1.6,2) F7(1.6,2) F8(2.4,2) F9(3.2,2) G1(-3.2,1.2) G2(-2.4,1.2) G3(-1.6,1.2) G7(1.6,1.2) G8(2.4,1.2) G9(3.2,1.2) H1(-3.2,0.4) H2(-2.4,0.4) H3(-1.6,0.4) H7(1.6,0.4) H8(2.4,0.4) H9(3.2,0.4) J1(-3.2,-0.4) J2(-2.4,-0.4) J3(-1.6,-0.4) J7(1.6,-0.4) J8(2.4,-0.4) J9(3.2,-0.4) K1(-3.2,-1.2) K2(-2.4,-1.2) K3(-1.6,-1.2) K7(1.6,-1.2) K8(2.4,-1.2) K9(3.2,-1.2) L1(-3.2,-2) L2(-2.4,-2) L3(-1.6,-2) L7(1.6,-2) L8(2.4,-2) L9(3.2,-2) M1(-3.2,-2.8) M2(-2.4,-2.8) M3(-1.6,-2.8) M7(1.6,-2.8) M8(2.4,-2.8) M9(3.2,-2.8) N1(-3.2,-3.6) N2(-2.4,-3.6) N3(-1.6,-3.6) N7(1.6,-3.6) N8(2.4,-3.6) N9(3.2,-3.6) P1(-3.2,-4.4) P2(-2.4,-4.4) P3(-1.6,-4.4) P7(1.6,-4.4) P8(2.4,-4.4) P9(3.2,-4.4) R1(-3.2,-5.2) R2(-2.4,-5.2) R3(-1.6,-5.2) R7(1.6,-5.2) R8(2.4,-5.2) R9(3.2,-5.2) T1(-3.2,-6) T2(-2.4,-6) T3(-1.6,-6) T7(1.6,-6) T8(2.4,-6) T9(3.2,-6)
  silkscreen extent -3.93,-6.55 3.8,6.68, body extent -3.8,-6.55 3.8,6.55, height 1.21
ICC_P-WFBGA153_13X11P5_P050 [mm]
  round 0.23 smd mask+0.05: A1(-3.25,-3.25) A2(-3.25,-2.75) A3(-3.25,-2.25) A4(-3.25,-1.75) A5(-3.25,-1.25) A6(-3.25,-0.75) A7(-3.25,-0.25) A8(-3.25,0.25) A9(-3.25,0.75) A10(-3.25,1.25) A11(-3.25,1.75) A12(-3.25,2.25) A13(-3.25,2.75) A14(-3.25,3.25) B1(-2.75,-3.25) B2(-2.75,-2.75) B3(-2.75,-2.25) B4(-2.75,-1.75) B5(-2.75,-1.25) B6(-2.75,-0.75) B7(-2.75,-0.25) B8(-2.75,0.25) B9(-2.75,0.75) B10(-2.75,1.25) B11(-2.75,1.75) B12(-2.75,2.25) B13(-2.75,2.75) B14(-2.75,3.25) C1(-2.25,-3.25) C2(-2.25,-2.75) C3(-2.25,-2.25) C4(-2.25,-1.75) C5(-2.25,-1.25) C6(-2.25,-0.75) C7(-2.25,-0.25) C8(-2.25,0.25) C9(-2.25,0.75) C10(-2.25,1.25) C11(-2.25,1.75) C12(-2.25,2.25) C13(-2.25,2.75) C14(-2.25,3.25) D1(-1.75,-3.25) D2(-1.75,-2.75) D3(-1.75,-2.25) D4(-1.75,-1.75) D12(-1.75,2.25) D13(-1.75,2.75) D14(-1.75,3.25) E1(-1.25,-3.25) E2(-1.25,-2.75) E3(-1.25,-2.25) E5(-1.25,-1.25) E6(-1.25,-0.75) E7(-1.25,-0.25) E8(-1.25,0.25) E9(-1.25,0.75) E10(-1.25,1.25) E12(-1.25,2.25) E13(-1.25,2.75) E14(-1.25,3.25) F1(-0.75,-3.25) F2(-0.75,-2.75) F3(-0.75,-2.25) F5(-0.75,-1.25) F10(-0.75,1.25) F12(-0.75,2.25) F13(-0.75,2.75) F14(-0.75,3.25) G1(-0.25,-3.25) G2(-0.25,-2.75) G3(-0.25,-2.25) G5(-0.25,-1.25) G10(-0.25,1.25) G12(-0.25,2.25) G13(-0.25,2.75) G14(-0.25,3.25) H1(0.25,-3.25) H2(0.25,-2.75) H3(0.25,-2.25) H5(0.25,-1.25) H10(0.25,1.25) H12(0.25,2.25) H13(0.25,2.75) H14(0.25,3.25) J1(0.75,-3.25) J2(0.75,-2.75) J3(0.75,-2.25) J5(0.75,-1.25) J10(0.75,1.25) J12(0.75,2.25) J13(0.75,2.75) J14(0.75,3.25) K1(1.25,-3.25) K2(1.25,-2.75) K3(1.25,-2.25) K5(1.25,-1.25) K6(1.25,-0.75) K7(1.25,-0.25) K8(1.25,0.25) K9(1.25,0.75) K10(1.25,1.25) K12(1.25,2.25) K13(1.25,2.75) K14(1.25,3.25) L1(1.75,-3.25) L2(1.75,-2.75) L3(1.75,-2.25) L12(1.75,2.25) L13(1.75,2.75) L14(1.75,3.25) M1(2.25,-3.25) M2(2.25,-2.75) M3(2.25,-2.25) M4(2.25,-1.75) M5(2.25,-1.25) M6(2.25,-0.75) M7(2.25,-0.25) M8(2.25,0.25) M9(2.25,0.75) M10(2.25,1.25) M11(2.25,1.75) M12(2.25,2.25) M13(2.25,2.75) M14(2.25,3.25) N1(2.75,-3.25) N2(2.75,-2.75) N3(2.75,-2.25) N4(2.75,-1.75) N5(2.75,-1.25) N6(2.75,-0.75) N7(2.75,-0.25) N8(2.75,0.25) N9(2.75,0.75) N10(2.75,1.25) N11(2.75,1.75) N12(2.75,2.25) N13(2.75,2.75) N14(2.75,3.25) P1(3.25,-3.25) P2(3.25,-2.75) P3(3.25,-2.25) P4(3.25,-1.75) P5(3.25,-1.25) P6(3.25,-0.75) P7(3.25,-0.25) P8(3.25,0.25) P9(3.25,0.75) P10(3.25,1.25) P11(3.25,1.75) P12(3.25,2.25) P13(3.25,2.75) P14(3.25,3.25)
  silkscreen extent -6.78,-6.02 6.63,5.87, body extent -6.55,-5.8 6.55,5.8, height 1
ICC_QFN56-EPAD_6P5X6P5_P040 [mm] "MCD-03000"
  rect 0.55x0.21 smd mask+0.05: 1(-3.245,2.6) 14(-3.245,-2.6) 29(3.245,-2.6) 42(3.245,2.6)
  rect 0.7x0.21 smd mask+0.05: 2(-3.17,2.2) 3(-3.17,1.8) 4(-3.17,1.4) 5(-3.17,1) 6(-3.17,0.6) 7(-3.17,0.2) 8(-3.17,-0.2) 9(-3.17,-0.6) 10(-3.17,-1) 11(-3.17,-1.4) 12(-3.17,-1.8) 13(-3.17,-2.2) 30(3.17,-2.2) 31(3.17,-1.8) 32(3.17,-1.4) 33(3.17,-1) 34(3.17,-0.6) 35(3.17,-0.2) 36(3.17,0.2) 37(3.17,0.6) 38(3.17,1) 39(3.17,1.4) 40(3.17,1.8) 41(3.17,2.2)
  rect 0.21x0.55 smd mask+0.05: 15(-2.6,-3.245) 28(2.6,-3.245) 43(2.6,3.245) 56(-2.6,3.245)
  rect 0.21x0.7 smd mask+0.05: 16(-2.2,-3.17) 17(-1.8,-3.17) 18(-1.4,-3.17) 19(-1,-3.17) 20(-0.6,-3.17) 21(-0.2,-3.17) 22(0.2,-3.17) 23(0.6,-3.17) 24(1,-3.17) 25(1.4,-3.17) 26(1.8,-3.17) 27(2.2,-3.17) 44(2.2,3.17) 45(1.8,3.17) 46(1.4,3.17) 47(1,3.17) 48(0.6,3.17) 49(0.2,3.17) 50(-0.2,3.17) 51(-0.6,3.17) 52(-1,3.17) 53(-1.4,3.17) 54(-1.8,3.17) 55(-2.2,3.17)
  rect 4.7x4.7 smd mask+0.05: 57(0,0)
  Top Layer region: -2.97,2.495 -2.82,2.495 -2.82,2.555 -2.97,2.705
  Top Layer region: -2.97,-2.495 -2.82,-2.495 -2.82,-2.555 -2.97,-2.705
  Top Layer region: -2.495,2.97 -2.495,2.82 -2.555,2.82 -2.705,2.97
  Top Layer region: 2.97,-2.495 2.82,-2.495 2.82,-2.555 2.97,-2.705
  Top Layer region: 2.495,-2.97 2.495,-2.82 2.555,-2.82 2.705,-2.97
  Top Layer region: 2.97,2.495 2.82,2.495 2.82,2.555 2.97,2.705
  Top Layer region: 2.495,2.97 2.495,2.82 2.555,2.82 2.705,2.97
  Top Layer region: -2.495,-2.97 -2.495,-2.82 -2.555,-2.82 -2.705,-2.97
  silkscreen extent -3.44,3 -3.01,3.42, body extent -3.25,-3.25 3.25,3.25, height 0.91
ICC_VFBGA361_10X10_P050 [mm] "MCD-03768"
  round 0.23 smd mask+0.05: A1(-4.5,4.5) A2(-4,4.5) A3(-3.5,4.5) A4(-3,4.5) A5(-2.5,4.5) A6(-2,4.5) A7(-1.5,4.5) A8(-1,4.5) A9(-0.5,4.5) A10(0,4.5) A11(0.5,4.5) A12(1,4.5) A13(1.5,4.5) A14(2,4.5) A15(2.5,4.5) A16(3,4.5) A17(3.5,4.5) A18(4,4.5) A19(4.5,4.5) B1(-4.5,4) B2(-4,4) B3(-3.5,4) B4(-3,4) B5(-2.5,4) B6(-2,4) B7(-1.5,4) B8(-1,4) B9(-0.5,4) B10(0,4) B11(0.5,4) B12(1,4) B13(1.5,4) B14(2,4) B15(2.5,4) B16(3,4) B17(3.5,4) B18(4,4) B19(4.5,4) C1(-4.5,3.5) C2(-4,3.5) C3(-3.5,3.5) C4(-3,3.5) C5(-2.5,3.5) C6(-2,3.5) C7(-1.5,3.5) C8(-1,3.5) C9(-0.5,3.5) C10(0,3.5) C11(0.5,3.5) C12(1,3.5) C13(1.5,3.5) C14(2,3.5) C15(2.5,3.5) C16(3,3.5) C17(3.5,3.5) C18(4,3.5) C19(4.5,3.5) D1(-4.5,3) D2(-4,3) D3(-3.5,3) D4(-3,3) D5(-2.5,3) D6(-2,3) D7(-1.5,3) D8(-1,3) D9(-0.5,3) D10(0,3) D11(0.5,3) D12(1,3) D13(1.5,3) D14(2,3) D15(2.5,3) D16(3,3) D17(3.5,3) D18(4,3) D19(4.5,3) E1(-4.5,2.5) E2(-4,2.5) E3(-3.5,2.5) E4(-3,2.5) E5(-2.5,2.5) E6(-2,2.5) E7(-1.5,2.5) E8(-1,2.5) E9(-0.5,2.5) E10(0,2.5) E11(0.5,2.5) E12(1,2.5) E13(1.5,2.5) E14(2,2.5) E15(2.5,2.5) E16(3,2.5) E17(3.5,2.5) E18(4,2.5) E19(4.5,2.5) F1(-4.5,2) F2(-4,2) F3(-3.5,2) F4(-3,2) F5(-2.5,2) F6(-2,2) F7(-1.5,2) F8(-1,2) F9(-0.5,2) F10(0,2) F11(0.5,2) F12(1,2) F13(1.5,2) F14(2,2) F15(2.5,2) F16(3,2) F17(3.5,2) F18(4,2) F19(4.5,2) G1(-4.5,1.5) G2(-4,1.5) G3(-3.5,1.5) G4(-3,1.5) G5(-2.5,1.5) G6(-2,1.5) G7(-1.5,1.5) G8(-1,1.5) G9(-0.5,1.5) G10(0,1.5) G11(0.5,1.5) G12(1,1.5) G13(1.5,1.5) G14(2,1.5) G15(2.5,1.5) G16(3,1.5) G17(3.5,1.5) G18(4,1.5) G19(4.5,1.5) H1(-4.5,1) H2(-4,1) H3(-3.5,1) H4(-3,1) H5(-2.5,1) H6(-2,1) H7(-1.5,1) H8(-1,1) H9(-0.5,1) H10(0,1) H11(0.5,1) H12(1,1) H13(1.5,1) H14(2,1) H15(2.5,1) H16(3,1) H17(3.5,1) H18(4,1) H19(4.5,1) J1(-4.5,0.5) J2(-4,0.5) J3(-3.5,0.5) J4(-3,0.5) J5(-2.5,0.5) J6(-2,0.5) J7(-1.5,0.5) J8(-1,0.5) J9(-0.5,0.5) J10(0,0.5) J11(0.5,0.5) J12(1,0.5) J13(1.5,0.5) J14(2,0.5) J15(2.5,0.5) J16(3,0.5) J17(3.5,0.5) J18(4,0.5) J19(4.5,0.5) K1(-4.5,0) K2(-4,0) K3(-3.5,0) K4(-3,0) K5(-2.5,0) K6(-2,0) K7(-1.5,0) K8(-1,0) K9(-0.5,0) K10(0,0) K11(0.5,0) K12(1,0) K13(1.5,0) K14(2,0) K15(2.5,0) K16(3,0) K17(3.5,0) K18(4,0) K19(4.5,0) L1(-4.5,-0.5) L2(-4,-0.5) L3(-3.5,-0.5) L4(-3,-0.5) L5(-2.5,-0.5) L6(-2,-0.5) L7(-1.5,-0.5) L8(-1,-0.5) L9(-0.5,-0.5) L10(0,-0.5) L11(0.5,-0.5) L12(1,-0.5) L13(1.5,-0.5) L14(2,-0.5) L15(2.5,-0.5) L16(3,-0.5) L17(3.5,-0.5) L18(4,-0.5) L19(4.5,-0.5) M1(-4.5,-1) M2(-4,-1) M3(-3.5,-1) M4(-3,-1) M5(-2.5,-1) M6(-2,-1) M7(-1.5,-1) M8(-1,-1) M9(-0.5,-1) M10(0,-1) M11(0.5,-1) M12(1,-1) M13(1.5,-1) M14(2,-1) M15(2.5,-1) M16(3,-1) M17(3.5,-1) M18(4,-1) M19(4.5,-1) N1(-4.5,-1.5) N2(-4,-1.5) N3(-3.5,-1.5) N4(-3,-1.5) N5(-2.5,-1.5) N6(-2,-1.5) N7(-1.5,-1.5) N8(-1,-1.5) N9(-0.5,-1.5) N10(0,-1.5) N11(0.5,-1.5) N12(1,-1.5) N13(1.5,-1.5) N14(2,-1.5) N15(2.5,-1.5) N16(3,-1.5) N17(3.5,-1.5) N18(4,-1.5) N19(4.5,-1.5) P1(-4.5,-2) P2(-4,-2) P3(-3.5,-2) P4(-3,-2) P5(-2.5,-2) P6(-2,-2) P7(-1.5,-2) P8(-1,-2) P9(-0.5,-2) P10(0,-2) P11(0.5,-2) P12(1,-2) P13(1.5,-2) P14(2,-2) P15(2.5,-2) P16(3,-2) P17(3.5,-2) P18(4,-2) P19(4.5,-2) R1(-4.5,-2.5) R2(-4,-2.5) R3(-3.5,-2.5) R4(-3,-2.5) R5(-2.5,-2.5) R6(-2,-2.5) R7(-1.5,-2.5) R8(-1,-2.5) R9(-0.5,-2.5) R10(0,-2.5) R11(0.5,-2.5) R12(1,-2.5) R13(1.5,-2.5) R14(2,-2.5) R15(2.5,-2.5) R16(3,-2.5) R17(3.5,-2.5) R18(4,-2.5) R19(4.5,-2.5) T1(-4.5,-3) T2(-4,-3) T3(-3.5,-3) T4(-3,-3) T5(-2.5,-3) T6(-2,-3) T7(-1.5,-3) T8(-1,-3) T9(-0.5,-3) T10(0,-3) T11(0.5,-3) T12(1,-3) T13(1.5,-3) T14(2,-3) T15(2.5,-3) T16(3,-3) T17(3.5,-3) T18(4,-3) T19(4.5,-3) U1(-4.5,-3.5) U2(-4,-3.5) U3(-3.5,-3.5) U4(-3,-3.5) U5(-2.5,-3.5) U6(-2,-3.5) U7(-1.5,-3.5) U8(-1,-3.5) U9(-0.5,-3.5) U10(0,-3.5) U11(0.5,-3.5) U12(1,-3.5) U13(1.5,-3.5) U14(2,-3.5) U15(2.5,-3.5) U16(3,-3.5) U17(3.5,-3.5) U18(4,-3.5) U19(4.5,-3.5) V1(-4.5,-4) V2(-4,-4) V3(-3.5,-4) V4(-3,-4) V5(-2.5,-4) V6(-2,-4) V7(-1.5,-4) V8(-1,-4) V9(-0.5,-4) V10(0,-4) V11(0.5,-4) V12(1,-4) V13(1.5,-4) V14(2,-4) V15(2.5,-4) V16(3,-4) V17(3.5,-4) V18(4,-4) V19(4.5,-4) W1(-4.5,-4.5) W2(-4,-4.5) W3(-3.5,-4.5) W4(-3,-4.5) W5(-2.5,-4.5) W6(-2,-4.5) W7(-1.5,-4.5) W8(-1,-4.5) W9(-0.5,-4.5) W10(0,-4.5) W11(0.5,-4.5) W12(1,-4.5) W13(1.5,-4.5) W14(2,-4.5) W15(2.5,-4.5) W16(3,-4.5) W17(3.5,-4.5) W18(4,-4.5) W19(4.5,-4.5)
  silkscreen extent -5.25,-5 5,5.2, body extent -5,-5 5,5, height 0.82
IND_2016_MURATA_LQM2MPN2R2NG0 [mm]
  rect 0.8x1.8 smd mask+0.05: 1(-0.8,0) 2(0.8,0)
  silkscreen extent -0.28,-0.87 0.28,0.87, body extent -1.07,-0.87 1.08,0.87, height 1
IND_2520_TOKO_DFE252012P [mm]
  rect 0.8x2 smd mask+0.05: 1(-1,0) 2(1,0)
  silkscreen extent -1.35,-1.12 1.35,1.12, body extent -1.35,-1.1 1.35,1.1, height 2
LED_0603_OSRAM_LG-Q396-PS-35_GREEN_1A2K_H0P4 [mm]
  rect 0.8x0.8 smd mask+0.05: 1(-0.75,0) 2(0.75,0)
  silkscreen extent -0.85,-0.53 1.28,0.53, body extent -0.85,-0.45 0.85,0.45, height 0.6
LINK200 [mm]
  rect 0.2x0.35 smd paste-10 mask+0.05: 1(0,-0.225) 2(0,0.225)
R0201_H0P23 [mm] "MCD-00702"
  rect 0.4x0.5 smd mask+0.05: 1(-0.3,0) 2(0.3,0)
  body extent -0.32,-0.17 0.32,0.17, height 0.26
R0402 [mm]
  rect 0.51x0.7 smd mask+0.05: 1(-0.45,0) 2(0.45,0)
  body extent -0.52,-0.3 0.52,0.3, height 0.4
R0603 [mm]
  rect 0.64x1 smd mask+0.05: 1(-0.7,0) 2(0.7,0)
  silkscreen extent -1.05,-0.58 1.05,0.58, body extent -0.9,-0.5 0.9,0.5, height 0.56
SWI_WE_434121025816 [mm] "MCD-03492"
  rect 1.5x1.4 smd: 1(-3.25,0) 2(3.25,0)
  silkscreen extent -3,-1.95 3,1.95, body extent -3.65,-1.95 3.65,1.95, height 2.51
TP_SMD_1MM [mm]
  round 1 smd paste-10 mask+0.05: 1(0,0)
  silkscreen extent -0.7,-0.7 0.7,0.7

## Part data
B2: library part MCD-03492, "Switch tactile, SPST-NO, 50mA, 12V, 6x3.8mm", Manufacturer="WURTH ELEKTRONIC", Manufacturer_Part_Number=434121025816, Package=6x3.8mm
C1 C2 C3 C4 C5: library part MCD-02377, "Capacitor, MLCC, 1uF, 6.3V, X5R, +/-20%, 0201, T=0,3mm", Manufacturer=MURATA, Manufacturer_Part_Number=GRM033R60J105MEA2, Package=0201
C9 C70 C82 C94 C104 C105 C106 C118 C130 C144 C146 C160 C178 C179 C181 C218 C226 C239 C252 C255 C256 C257 C258 C259 C261 C265 C266: library part MCD-00006, "Capacitor, MLCC, 100nF, 16V, X7R, +/-10%, 0402, T=0.5mm", Alternate_Manufacturer=MURATA, Alternate_Manufacturer_Part_Number=GCM155R71C104KA55D, Manufacturer=YAGEO, Manufacturer_Part_Number=CC0402KRX7R7BB104, Package=0402
C14: library part MCD-01823, "Capacitor, MLCC, 2.2uF, 6V3, X5R,+/-10%, 0402, T=0.5mm", Alternate_Manufacturer=N/A, Manufacturer=MURATA, Manufacturer_Part_Number=GRM155R60J225KE95D, Package=0402
C15 C214 C250 C260: library part MCD-02377, "Capacitor, MLCC, 1uF, 6.3V, X5R, +/-20%, 0201, T=0,3mm", Alternate_Manufacturer=N/A, Manufacturer=MURATA, Manufacturer_Part_Number=GRM033R60J105MEA2, Package=0201
C16 C17 C201 C210 C212 C215 C219 C220 C234 C236 C237 C238 C240 C244 C246 C248 C251 C253: library part MCD-01535, "Capacitor, MLCC,100nF, 10V, X7R, +/-10%, 0201, T=0.3mm", Alternate_Manufacturer=N/A, Manufacturer=MURATA, Manufacturer_Part_Number=GRM033R61A104KE15, Package=0201
C18 C42: library part MCD-01796, "Capacitor, Tantalum, 100uF, 6V3, 40mR, +/-20%,  Type_B (3528 metric), T=1.9mm", Manufacturer=AVX, Manufacturer_Part_Number=TCJB107M006R0040, Package="3528 (metric)"
C19 C21 C152 C157 C186 C187 C193 C204 C206 C207: library part MCD-03139, "Capacitor, MLCC, 22uF, 10V, X5R, +/-20%, 0805, T=1,25mm", Manufacturer=MURATA, Manufacturer_Part_Number=GRM21BR61A226ME51L, Package=0805
C20 C29 C30 C32 C38 C184 C199: library part MCD-00099, "Capacitor, MLCC, 10uF, 10V, X5R, +/-10%, 0603, T=0,8mm", Alternate_Manufacturer=N/A, Manufacturer=MURATA, Manufacturer_Part_Number=GRM188R61A106KE69D, Package=0603
C22 C23 C24 C26 C27 C28 C34 C35 C36 C37 C41 C183 C200 C202: library part MCD-00100, "Capacitor, MLCC, 22uF, 6V3, X5R, +/-20%, 0603, T=0,8mm", Alternate_Manufacturer=N/A, Manufacturer=MURATA, Manufacturer_Part_Number=GRM188R60J226MEA0J, Package=0603
C33: library part MCD-00011, "Capacitor, MLCC, 10nF, 16V, X7R, 10%, 0402, T=0.5mm", Manufacturer=YAGEO, Manufacturer_Part_Number=CC0402KRX7R7BB103, Package=C0402
C39 C40 C145 C254: library part MCD-03140, "Capacitor, MLCC, 10uF, 6.3V, X5R, +/-20%, 0402, T=0.5mm", Manufacturer=MURATA, Manufacturer_Part_Number=GRM155R60J106ME05D, Package=0402
C43 C153 C154 C188: library part MCD-00095, "Capacitor, MLCC, 1uF, 25V, X5R, +/-10%, 0402, T=0.5mm", Manufacturer=MURATA, Manufacturer_Part_Number=GRM155R61E105KA12, Package=0402
C79 C117 C128: library part MCD-02606, "Capacitor, MLCC, 2.2uF, 6.3V, X5R, +/-10%, 0402, T=0.5mm", Manufacturer=YAGEO, Manufacturer_Part_Number=CC0402KRX5R5BB225, Package=0402
C81 C86 C90 C92: library part MCD-00674, "Capacitor, MLCC, 6.8pF, 50V, NPO, +-0.25pF, 0402, T=0.5mm", Alternate_Manufacturer=N/A, Manufacturer=YAGEO, Manufacturer_Part_Number=CC0402CRNPO9BN6R8, Package=0402
C87: library part MCD-00006, "Capacitor,100nF,16V,X7R,10%,0402", Alternate_Manufacturer=MURATA, Alternate_Manufacturer_Part_Number=GCM155R71C104KA55D, Manufacturer=YAGEO, Manufacturer_Part_Number=CC0402KRX7R7BB104, Package=0402
C91 C141 C142 C156 C189 C190 C208 C209 C217: library part MCD-01356, "Capacitor, MLCC, 4.7uF, 6V3, X5R, +/-20%, 0402, T=0.5mm", Manufacturer=MURATA, Manufacturer_Part_Number=GRM155R60J475ME47, Package=0402
C112 C172: library part MCD-01341, "Capacitor, MLCC, 10uF, 6V3, X5R, +/-20%, 0603, T=0,8mm", Alternate_Manufacturer=MURATA, Alternate_Manufacturer_Part_Number=GRM188R60J106ME84D, Manufacturer_Part_Number=GRM188R60J106ME47D, Package=0603
C155: library part MCD-02198, "Capacitor, MLCC, 10nF, 50V, X7R, +/-10%, 0402, T=0.5mm", Manufacturer=YAGEO, Manufacturer_Part_Number=CC0402KRX7R9BB103, Package=0402
C175 C177 C191 C192 C194 C195 C196 C197 C203 C205 C211 C213 C283 C284 C287 C289 C299 C300 C304 C306 C307: library part MCD-01533, "Capacitor, MLCC, 1uF, 6V3, X5R, +/-20%, 0201,T=0.3mm", Alternate_Manufacturer=MURATA, Alternate_Manufacturer_Part_Number=GRM033R60J105MEA2, Manufacturer_Part_Number=GRM033R60J105ME11, Package=0201
C225: library part MCD-01534, "Capacitor, MLCC, 4,7uF, 6V3, X5R, +/-20%, 0201, T=0.5mm", Alternate_Manufacturer=N/A, Manufacturer=MURATA, Manufacturer_Part_Number=GRM035R60J475ME15, Package=0201
C235: library part MCD-02235, "Capacitor, MLCC, 2.2uF, 10V, X5R,+/-10%, 0201, T=0.5mm", Manufacturer=MURATA, Manufacturer_Part_Number=GRM033R61A225KE47D, Package=0201
CN12: library part MCD-00655, "Header 2 circuits, 1.25mm Pitch ,  Vertical, with Friction Lock", Alternate_Manufacturer=N/A, Manufacturer=MOLEX, Manufacturer_Part_Number=53047-0210
D6: library part MCD-03280, "Diode, Schottky, Dual Common Cathode, 0V3, 300mA, 40V, SOT-23", Manufacturer=STMICROELECTRONICS, Manufacturer_Part_Number=BAT54CFILM, Package=SOT-23
D7: library part MCD-00034, Manufacturer=STMICROELECTRONICS, Manufacturer_HQ_COO=EU
L1 L6: library part MCD-03143, "Inductor, 2.2uH, +/-20%, Itemp= 1700mA, Isat= 2400mA, 0R140, 0806, T=1mm", Manufacturer=MURATA, Manufacturer_Part_Number=DFE201610E-2R2M{}P2, Package=0806
L2 L4: library part MCD-03142, "Inductor, 0.68uH, +/-20%, Itemp= 3900mA, Isat= 5400mA, 0R031, 1008, T=1.2mm", Manufacturer=MURATA, Manufacturer_Part_Number=DFE252012F-R68M{}P2, Package=1008
L3 L5 L7: library part MCD-03141, "Inductor, 0.68uH, +/-20%, Itemp= 3100mA, Isat= 4300mA, 0R043, 0806, T=1mm", Manufacturer=MURATA, Manufacturer_Part_Number=DFE201610E-R68M{}P2, Package=0806
LD11: library part MCD-00588, "LED Green, 0603 SMD, Forward Voltage Typ=2V, Max=2.5V", Alternate_Manufacturer="VISHAY SEMICONDUCTOR OPTO DIVISION", Alternate_Manufacturer_Part_Number=VLMTG1300-GS08, Manufacturer="OSRAM OPTO SEMICONDUCTORS", Manufacturer_Part_Number="LG Q396-PS-35", Package="LED 0603"
LNK1 LNK2 LNK4 LNK7 LNK8 LNK11: library part MCD-02777, "Track link on PCB 200um width for layout routing", Manufacturer=N/A
R2 R3 R46 R57 R59 R60 R64 R81 R267 R269 R286: library part MCD-00052, "Resistor,0R,0402,5%,1/16W", Alternate_Manufacturer=N/A, Manufacturer=YAGEO, Manufacturer_Part_Number=RC0402JR-070RL, Package=0402
R11: library part MCD-00056, "Resistor, 0R, 0603, +/-5%, 1/10W", Manufacturer=YAGEO, Manufacturer_Part_Number=RC0603JR-070RL, Package=0603
R27 R176 R272: library part MCD-00053, "Resistor,10K,0402,1%,1/16W", Alternate_Manufacturer=N/A, Manufacturer=YAGEO, Manufacturer_Part_Number=RC0402FR-0710KL, Package=0402
R66: library part MCD-00058, "Resistor, 20R, 0402, +/-1%, 1/16W", Alternate_Manufacturer=N/A, Manufacturer=YAGEO, Manufacturer_Part_Number=RC0402FR-0720RL, Package=0402
R67: library part MCD-00052, "Resistor, 0R, 0402, +/-5%, 1/16W", Manufacturer=YAGEO, Manufacturer_Part_Number=RC0402JR-070RL, Package=0402
R101 R103 R104 R248: library part MCD-00053, "Resistor,10K,0402,1%,1/16W", Manufacturer=YAGEO, Manufacturer_Part_Number=RC0402FR-0710KL, Package=0402
R112 R113 R179: library part MCD-02253, "Resistor,240R,0201,1%,1/20W", Alternate_Manufacturer=N/A, Manufacturer=YAGEO, Manufacturer_Part_Number=RC0201FR-07240RL, Package=R0201
R116 R118: library part MCD-00061, "Resistor, 1K, 0402, +/-1%,1/16W", Manufacturer=YAGEO, Manufacturer_Part_Number=RC0402FR-071KL, Package=0402
R177: library part MCD-01819, "Resistor,100R,0402,0,5%,1/16W,±100ppm/°C", Alternate_Manufacturer=N/A, Manufacturer=YAGEO, Manufacturer_Part_Number=RC0402DR-07100RL, Package=0402
R210: library part MCD-00441, "Resistor,270R,0402,1%,1/16W", Manufacturer=YAGEO, Manufacturer_Part_Number=RC0402FR-07270RL, Package=0402
R252 R253 R254 R255 R256 R257 R258 R259 R263 R264 R265 R266 R268 R271 R273 R275 R276 R277 R278 R279 R280 R281 R282 R283 R284: library part MCD-00054, "Resistor, 56R, 0402, +/-1%, 1/16W", Alternate_Manufacturer=N/A, Manufacturer=YAGEO, Manufacturer_Part_Number=RC0402FR-0756RL, Package=0402
R260 R261: library part MCD-00068, "Resistor,1K5,0402,1%,1/16W", Manufacturer=YAGEO, Manufacturer_Part_Number=RC0402FR-071K5L, Package=0402
TP21: library part MCD-00074, "Test Point 1mm", Manufacturer=n/a
U14: library part MCD-03768, "MPU, dual core ARM cortex-A35 64-bit + M33 32-bit, 808KB SRAM, With Crypto", Manufacturer=STMICROELECTRONICS, Package=VFBGA361
U17: library part MCD-04020, "Memory, DDR4 SDRAM, 1V2, 32Gbit, 1.6GHz, FBGA96", Manufacturer=MICRON, Package=FBGA96
U26: library part MCD-03000, "STPMIC2", Manufacturer=STMICROELECTRONICS, Package=VQFN
U37: library part MCD-02799, "Memory, eMMC, 4GB, 15nm ,WFBGA , 153 pins", Manufacturer=KIOXIA, Manufacturer_Part_Number=THGBMTG5D1LBAIL, Package=WFBGA153
X1: library part MCD-01479, "Crystal, 32.768kHz, 6pF, +/-20ppm, 80K, 2.05x1.2mm", Manufacturer=NDK, Manufacturer_Part_Number=NX2012SA-32.768KHZ-EXS00A-MU00527, Package=2.05x1.2mm
X2: library part MCD-02344, "Crystal, 40MHz, 6pF, +/-20ppm, 80R, 1.6x1.2mm", Manufacturer=NDK, Manufacturer_Part_Number=NX1612SA-40MHZ-EXS00A-CS13836, Package=1.6x1.2mm

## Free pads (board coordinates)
  round 0.508 on Mech16: 1(39.085,-32.513) 1(87.94,-32.521)

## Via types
v1: diameter 0.5, hole 0.2, Top Layer to Bottom Layer, 292 vias
v2: diameter 0.26, hole 0.1, Top Layer to Signal Layer 1, 266 vias
v3: diameter 0.26, hole 0.1, Signal Layer 1 to Signal Layer 2, 143 vias
v4: diameter 0.4, hole 0.2, Signal Layer 1 to Signal Layer 4, 101 vias
v5: diameter 0.26, hole 0.1, Signal Layer 4 to Bottom Layer, 81 vias
v6: diameter 0.55, hole 0.35, Top Layer to Bottom Layer, 55 vias
v7: diameter 0.5, hole 0.2, Signal Layer 1 to Signal Layer 4, 1 vias

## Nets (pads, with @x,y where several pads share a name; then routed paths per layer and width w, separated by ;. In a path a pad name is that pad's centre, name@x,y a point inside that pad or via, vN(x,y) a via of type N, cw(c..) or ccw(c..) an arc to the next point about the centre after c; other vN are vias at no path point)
1V8: C118.2 C128.2 C152.2 C157.2 C193.2 C212.2 C220.2 C236.2 C237.2 C238.2 C240.2 C246.2 C253.2 L1.2 LNK1.2 R101.2 R103.2 R104.2 R248.2 R267.2 R269.1 U14.C5 U14.D3 U14.D16 U14.E15 U14.F8 U14.G6 U14.H6 U14.J4 U14.R13 U14.T13 U37.C6 U37.M4 U37.N4 U37.P3 U37.P5 | length 31.4
  Top Layer w0.1: U14.R13@71.975,31.65 v5(71.975,31.15) 71.975,31.125 U14.T13@72,31.1
  Top Layer w0.15: U37.P3@85.751,47.447 85.753,47.449 86.224,47.449 v1@86.225,47.45
  Top Layer w0.2: LNK1.2@39.998,42.487 v6(39.998,43.089) ; U37.C6@80.25,48.95 80.647,49.347 80.647,49.582 v1(80.725,49.66) ; U37.M4@84.751,47.947 U37.N4@85.251,47.947 ; U37.P3@85.751,47.447 U37.N4@85.251,47.947 ; U37.P5@85.751,48.447 U37.N4@85.251,47.947
  Top Layer w0.64: C152.2@38.898,43.089 v6(39.998,43.089)
  Top Layer w0.8: L1.2@36.893,41.314 36.893,43.039 36.943,43.089 C157.2@37.048,43.089
  Top Layer w0.9: C193.2@35.198,43.089 C157.2@36.943,43.089 ; C157.2@37.048,43.089 C152.2@38.898,43.089
  Signal Layer 1 w0.2: v2(68.475,35.15) v4(68.475,35.65)
  Bottom Layer w0.1: C237.2@67.38,36.95 67.717,37.287 67.717,37.392 v4(67.975,37.65) ; v4(68.475,35.65) 68.475,35.693 68.538,35.756 68.538,35.783 68.755,36.001 68.755,36.271 68.834,36.35 68.925,36.35 C212.2@69.05,36.475 ; v2(72.975,36.65) 72.975,36.95 73.175,37.15 v4(73.475,37.15) ; C128.2@86.754,47.704 C128.2@86.85,47.8
  Bottom Layer w0.2: R269.1@65.55,33.5 65.575,33.525 66.597,33.525 66.727,33.655 66.727,33.902 v5(67.475,34.65) ; v4(66.975,37.15) 67.2,36.925 C237.2@67.4,36.925 ; C237.2@67.4,36.93 67.455,36.875 67.475,36.875 67.635,36.715 67.635,35.796 67.856,35.575 67.97,35.575 C240.2@68.045,35.5 67.97,35.425 67.97,35.319 67.959,35.308 67.959,35.017 67.955,35.013 67.955,34.9 67.705,34.65 v5@67.491,34.65 ; v4(67.975,37.65) 67.975,38.025 C220.2@68.05,38.1 ; C240.2@68.113,35.568 v5@68.377,35.568 ; C212.2@69.1,36.4 69.225,36.4 v4(69.475,36.15) ; C253.2@71.333,30.745 71.336,30.748 71.948,30.748 C246.2@71.95,30.745 ; v5@71.95,31.125 v5(71.975,31.15) ; C246.2@71.975,30.745 v5@71.975,31.125 ; R101.2@79.211,48.058 79.261,48.058 79.416,48.213 79.416,48.505 79.916,49.006 79.916,49.008 80.071,49.163 C118.2@80.096,49.163 ; C118.2@80.175,49.11 80.715,49.65 v1@80.75,49.65 ; R103.2@85.007,49.244 85.605,49.244 ; R104.2@85.011,46.638 85.526,46.638 85.721,46.833 85.721,47.282 85.897,47.458 ; 85.703,48.212 85.676,48.239 85.676,49.174 85.605,49.244 ; R248.2@85.943,50.263 85.788,50.108 85.788,49.428 85.605,49.244 ; v1@86.225,47.45 86.479,47.704 C128.2@86.754,47.704
  Bottom Layer w0.3: 85.703,48.212 85.703,47.651 85.897,47.458 86.217,47.458 v1@86.225,47.45
  other v1: 86.215,47.45
  other v2: 71.975,31.15 67.475,34.65 68.475,35.65 69.475,36.15 66.975,37.15 73.475,37.15 67.975,37.65
  other v4: 71.975,31.15 67.475,34.65 72.975,36.65
  other v5: 68.475,35.65 69.475,36.15 72.975,36.65 66.975,37.15 73.475,37.15 67.975,37.65
1V8_FB: LNK1.1 U26.35 | length 5.1
  Top Layer w0.15: U26.35@39.598,37.109 39.598,39.45 39.573,39.475 39.573,41.612 LNK1.1@39.998,42.037
3V3: C21.2 C154.2 C204.2 C206.2 C207.2 L7.2 U26.3 U26.53 | length 15.3
  Top Layer w0.15: v1(34.308,30.116) 34.66,30.468 34.66,31.604 35.595,32.539 U26.53@36.228,32.539 ; U26.53@36.018,32.508 36.317,32.508 U26.53@36.348,32.539
  Top Layer w0.21: 37.371,29.736 37.598,29.964 U26.3@37.598,30.769
  Top Layer w0.3: C154.2@36.373,27.314 C154.2@36.398,27.314 v1@36.983,27.314
  Top Layer w0.4: C154.2@36.398,27.314 36.412,27.328 36.412,27.824 36.858,28.27 36.858,29.224 37.371,29.736
  Top Layer w0.9: C206.2@24.485,28.462 C21.2@29.898,28.462 31.26,28.462 L7.2@31.285,28.437
  other v1: 37.008,27.314
  other v6: 24.085,26.962 24.81,26.962 25.535,26.962 24.085,27.637 24.81,27.637 25.535,27.637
